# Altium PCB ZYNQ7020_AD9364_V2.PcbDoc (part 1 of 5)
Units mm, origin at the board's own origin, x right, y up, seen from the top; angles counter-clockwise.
Board outline 88.95 x 91.52 mm, 4 copper layers (Top Layer, Layer 1, Layer 2, Bottom Layer), stack 0.603 mm thick; 285 components, 278 nets, 1497 pads, 1247 vias.
Unrouted connection lines stored in the file: 367.
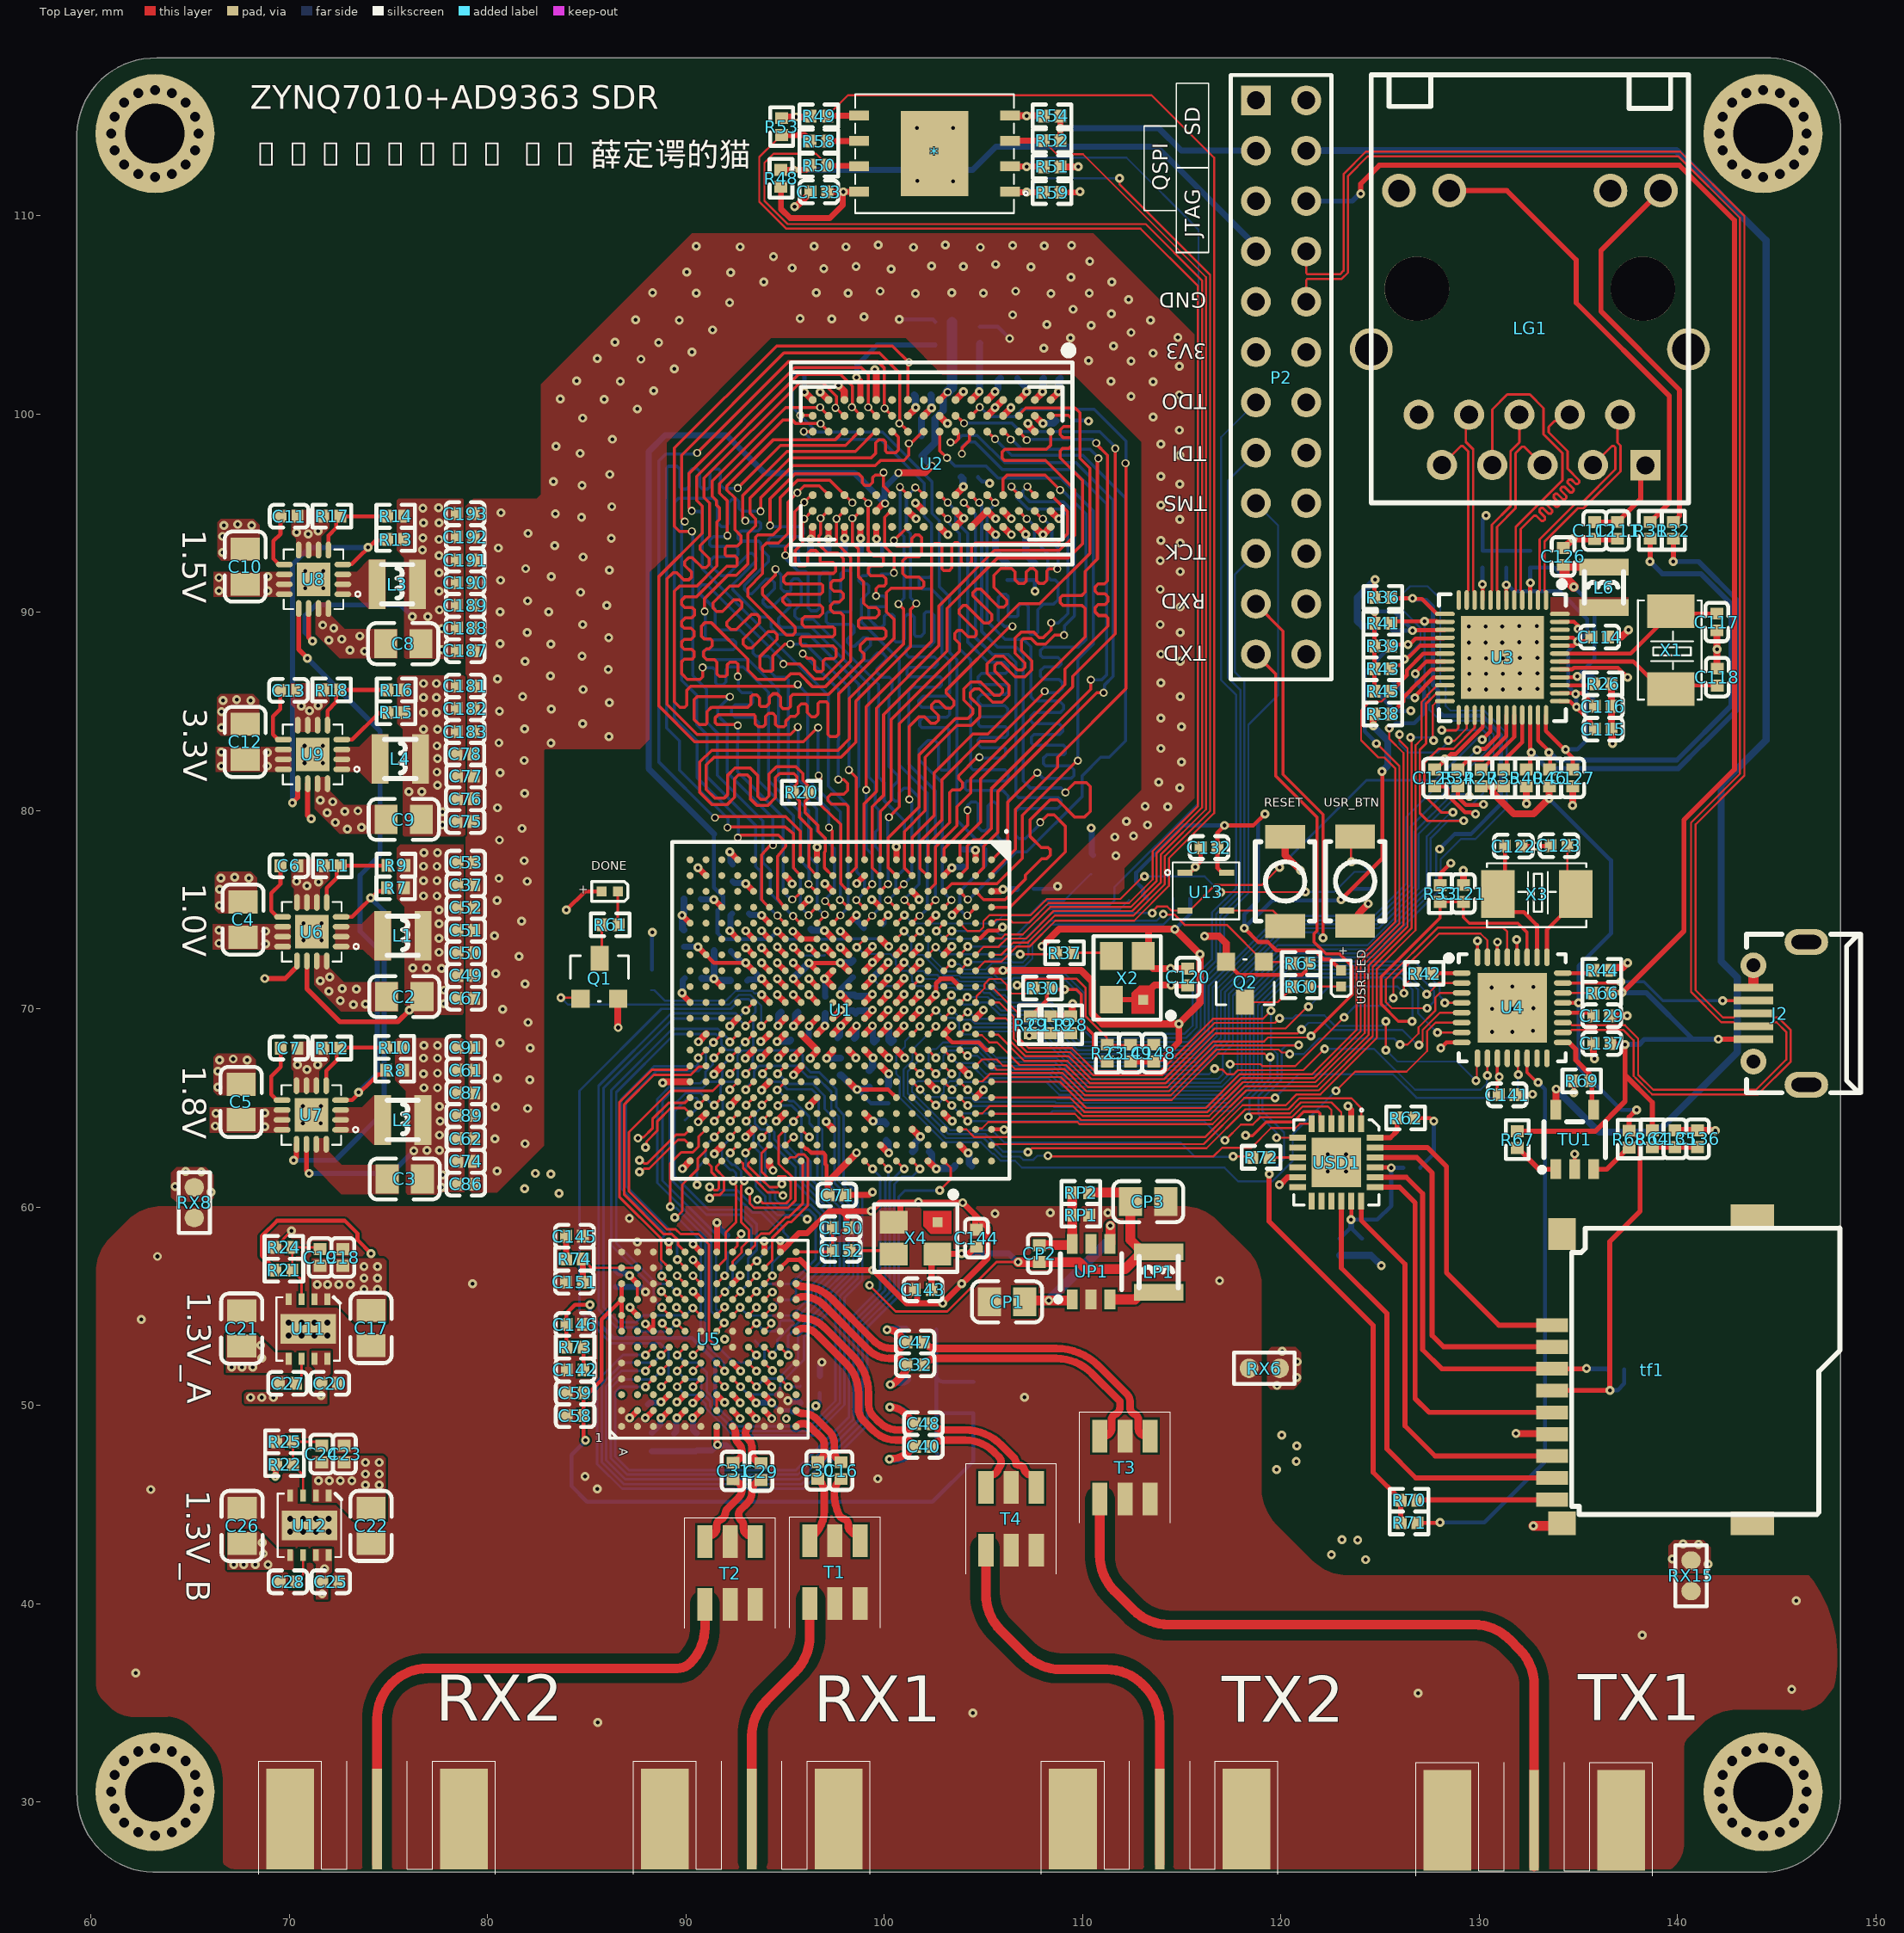
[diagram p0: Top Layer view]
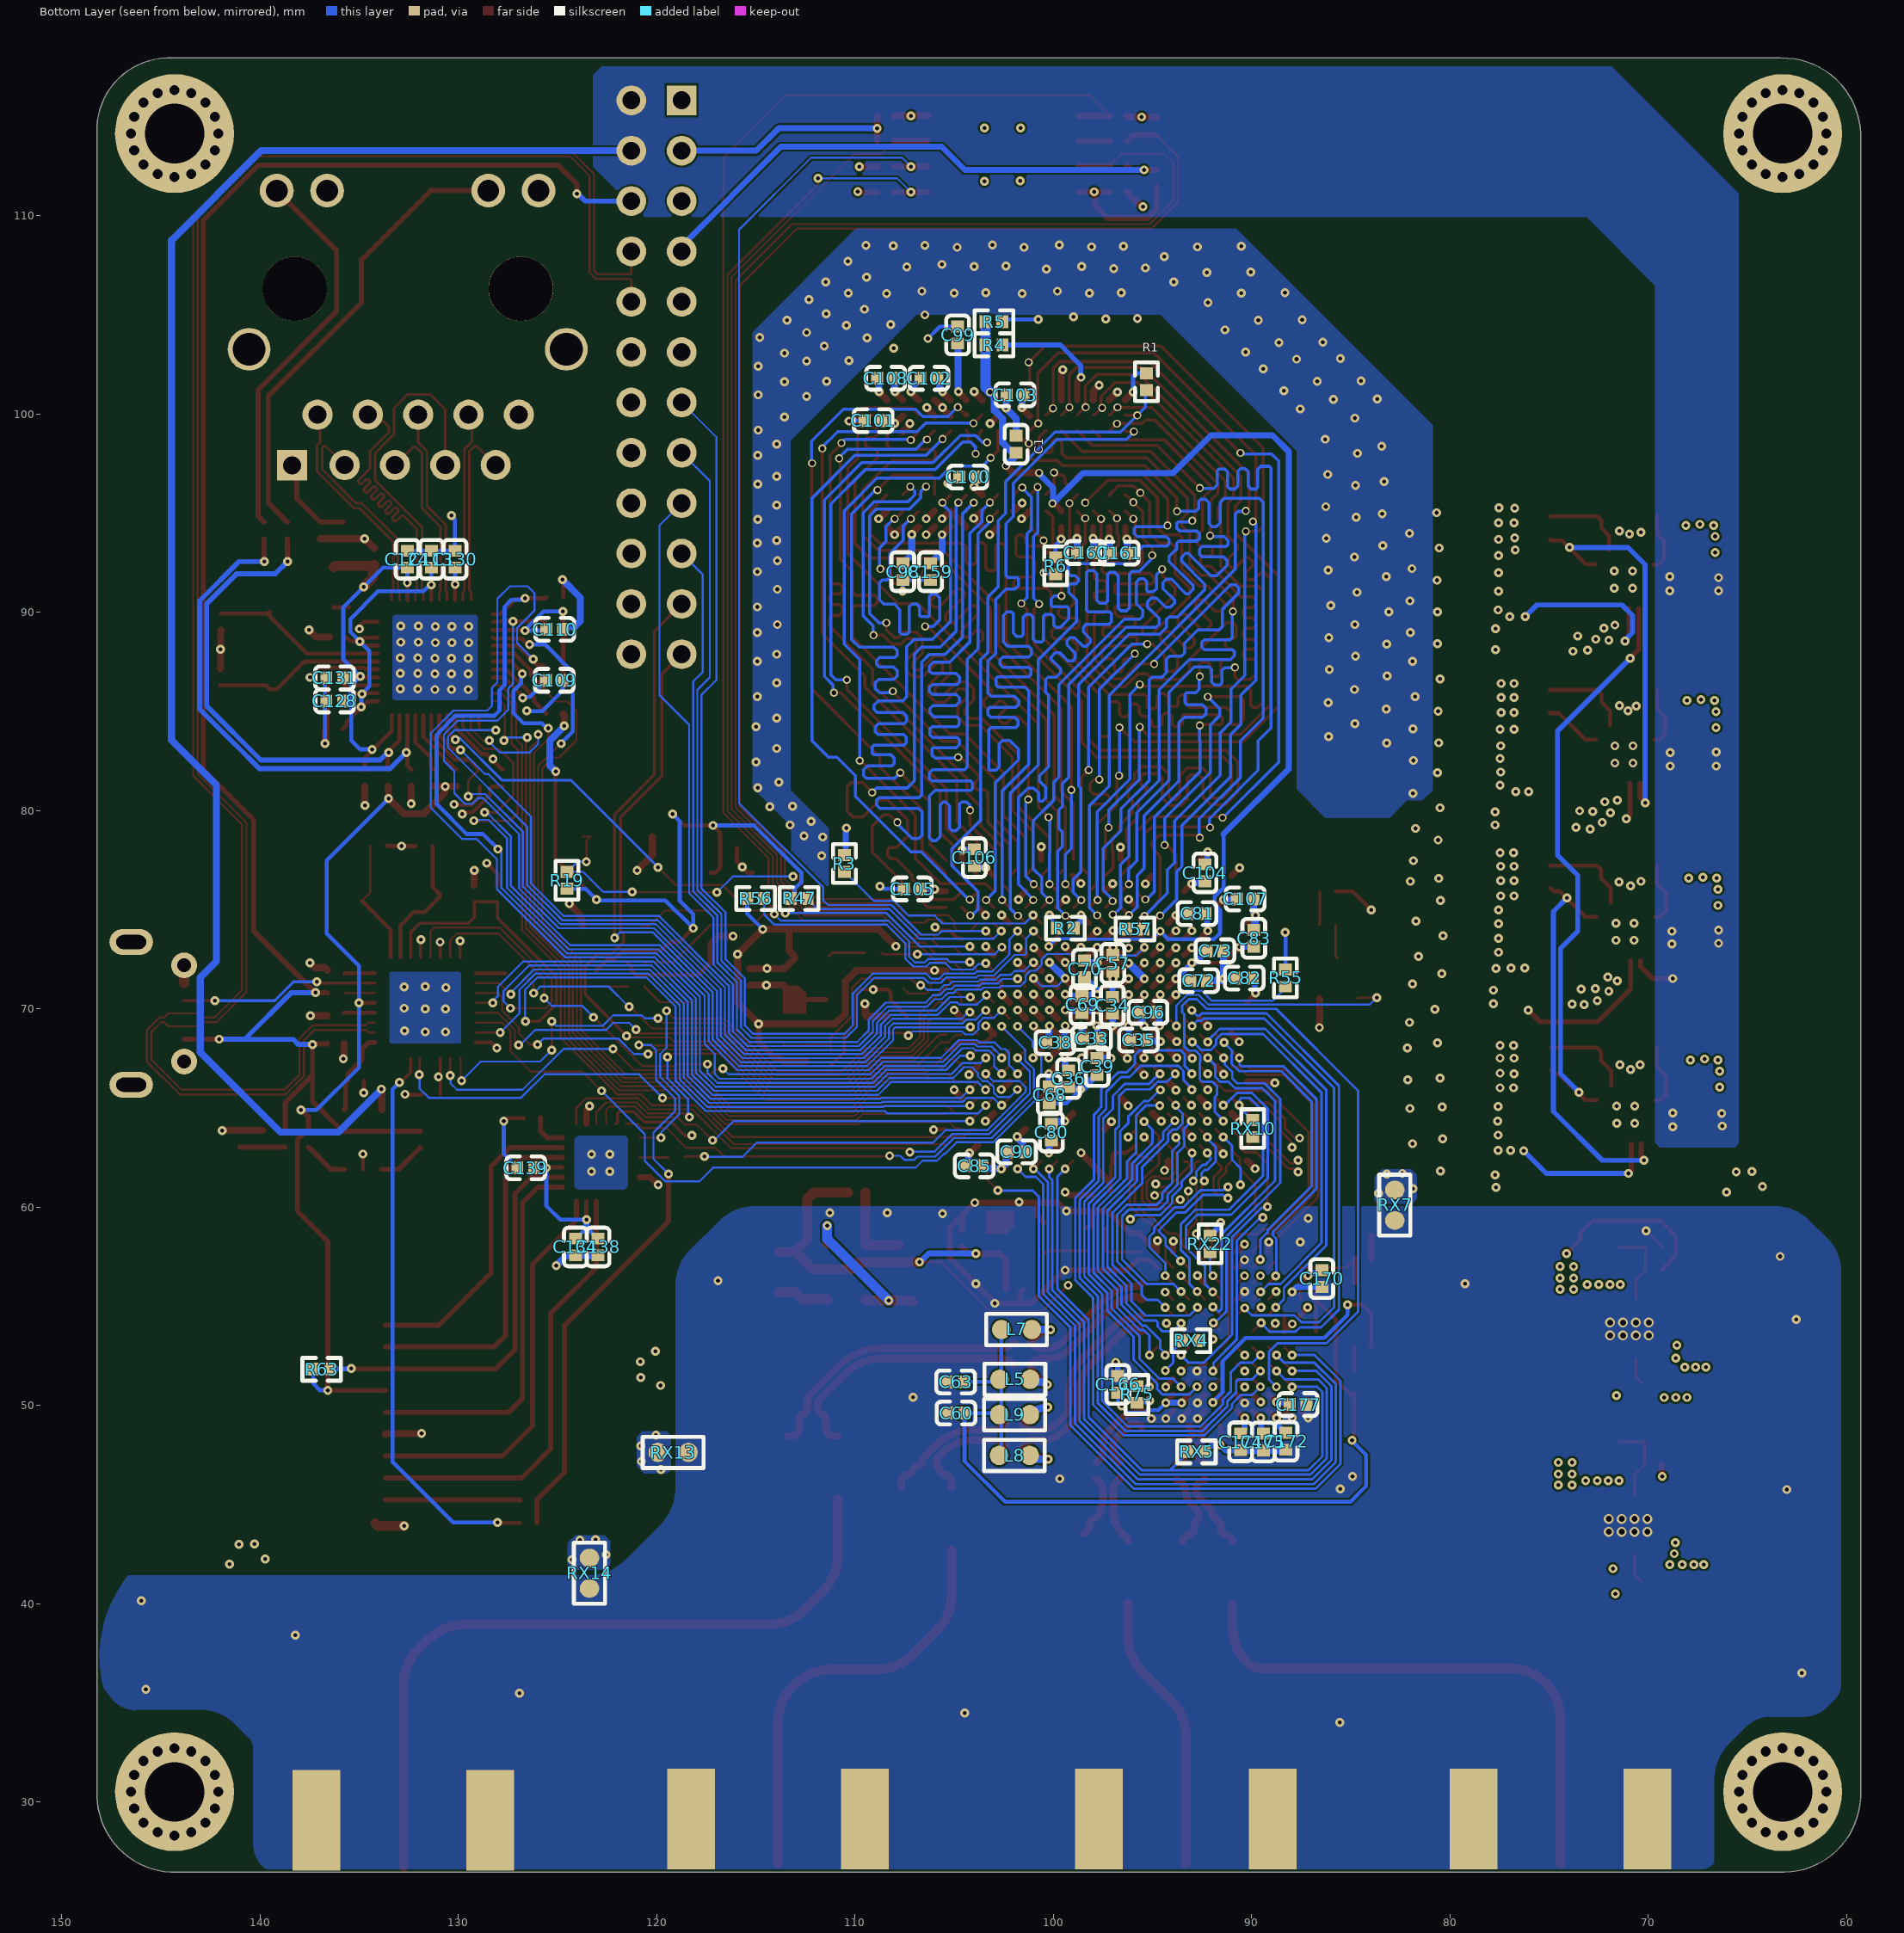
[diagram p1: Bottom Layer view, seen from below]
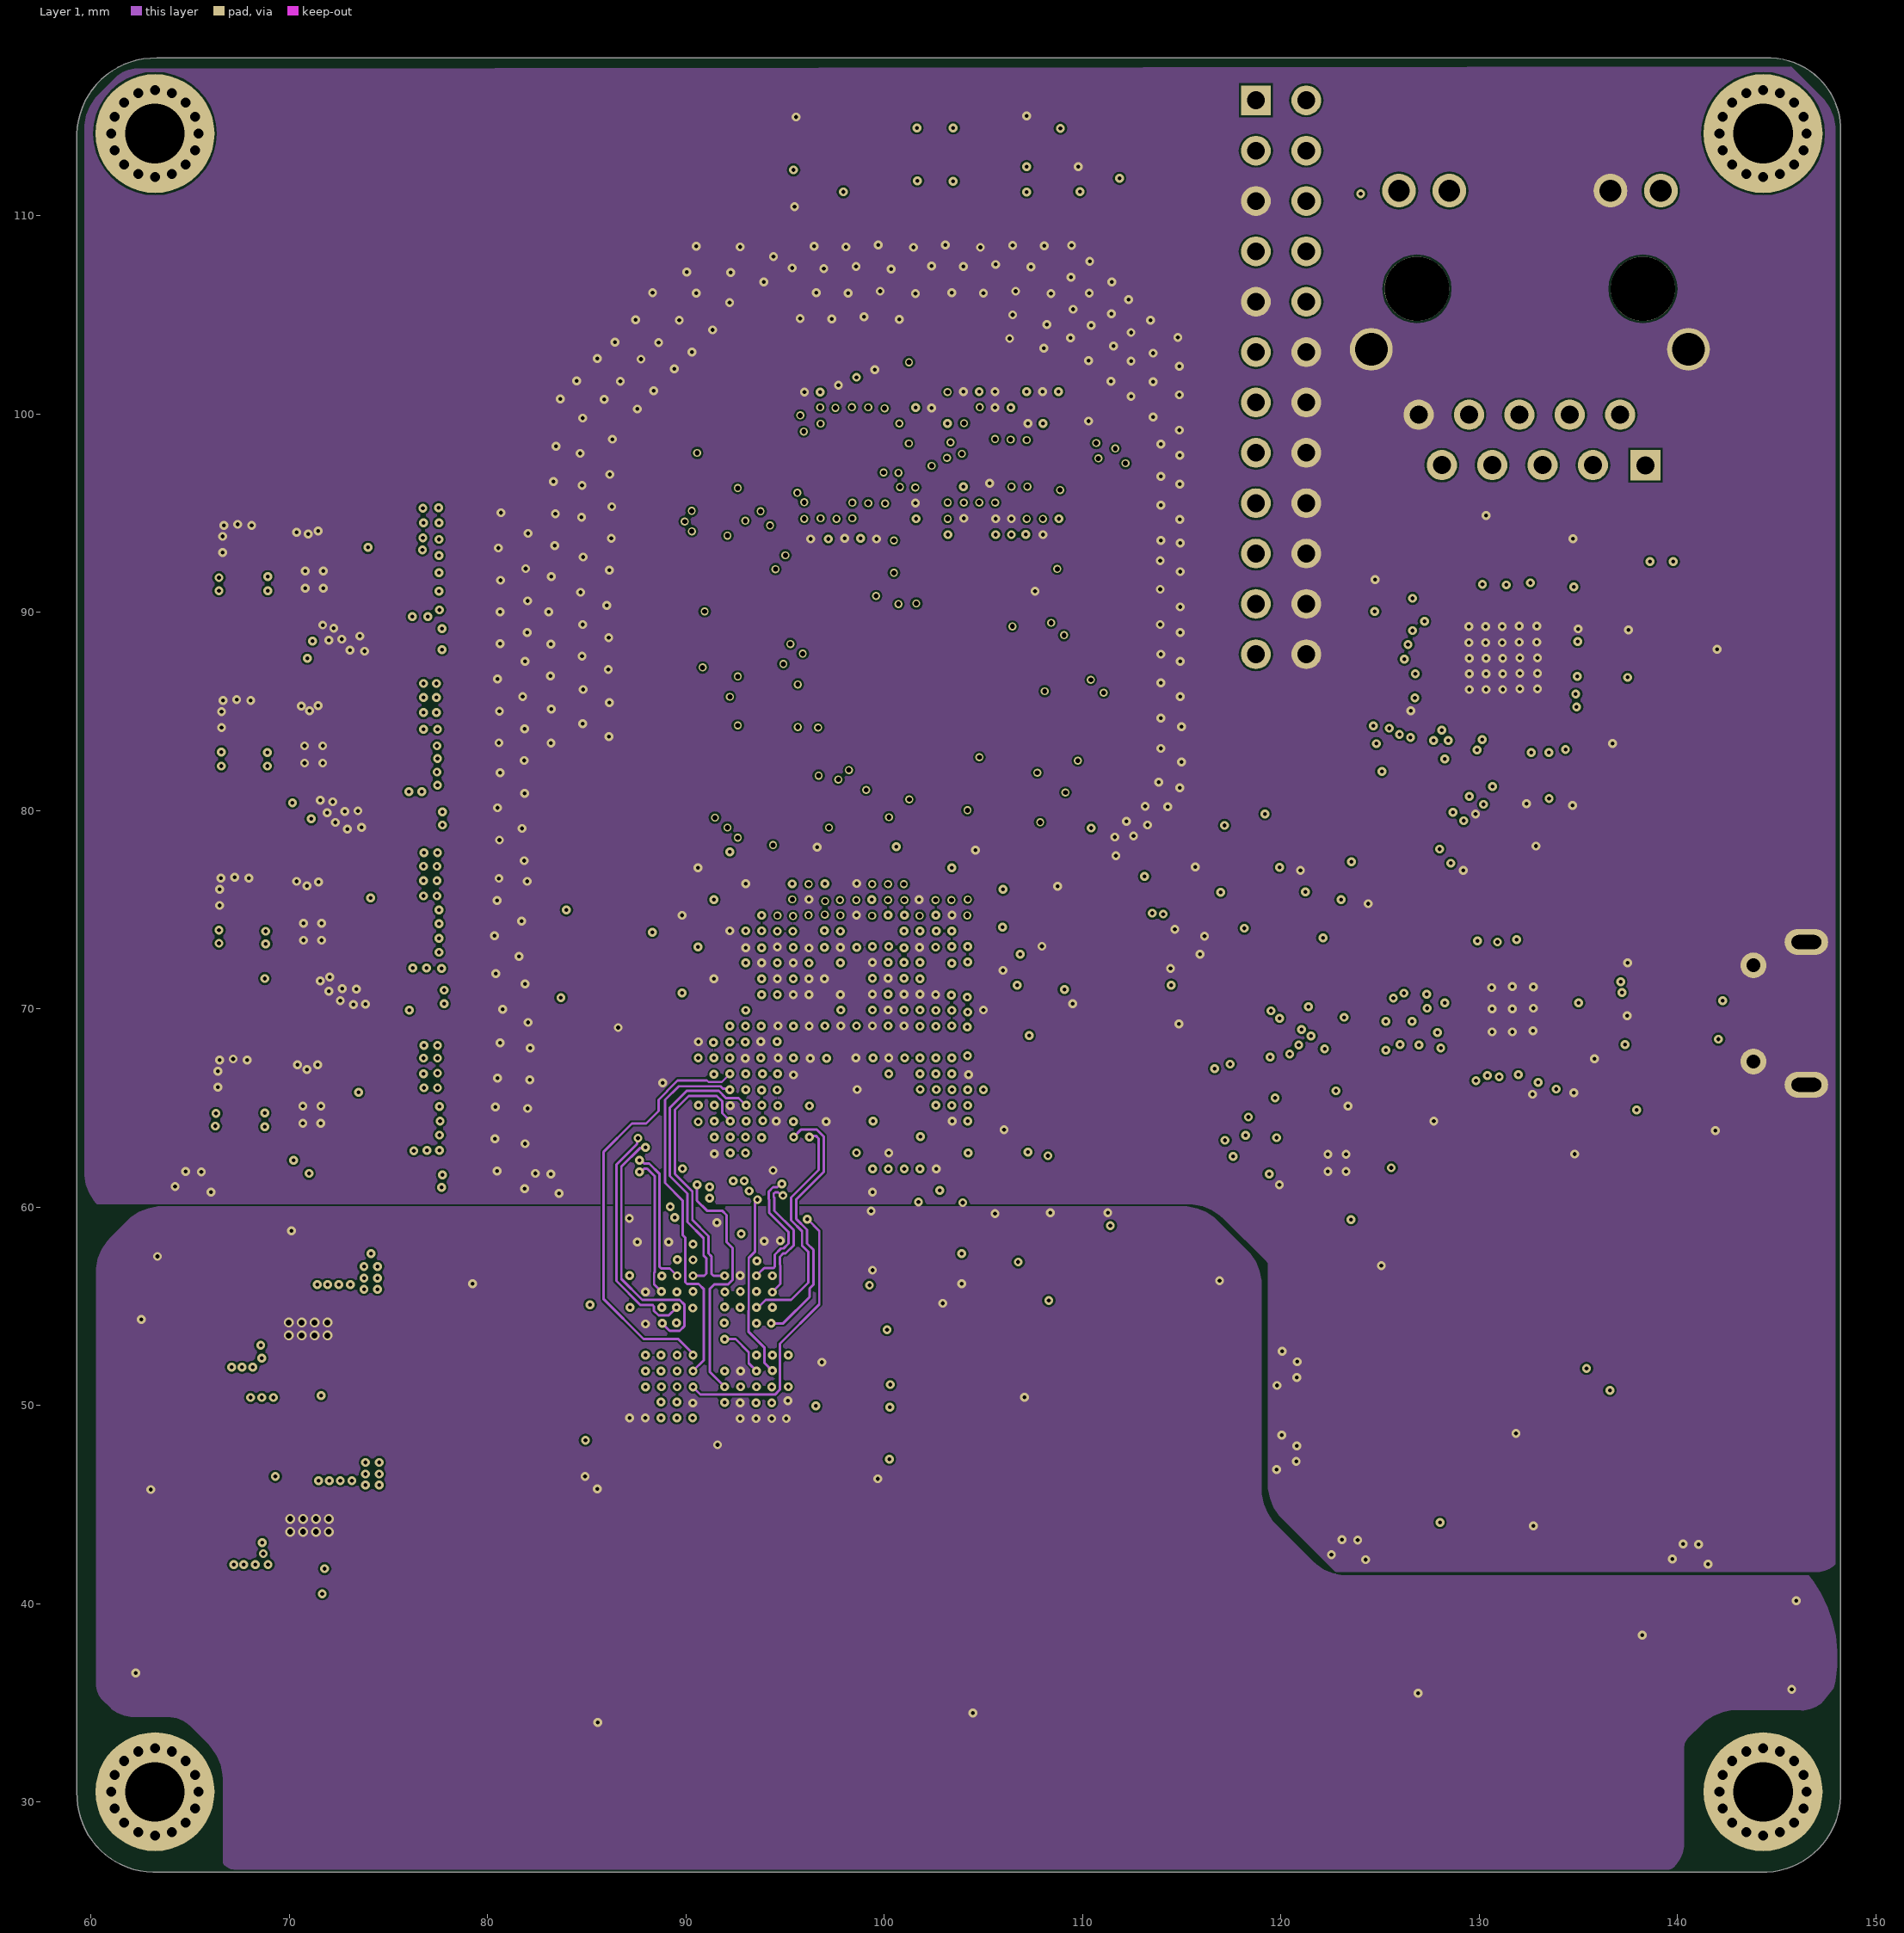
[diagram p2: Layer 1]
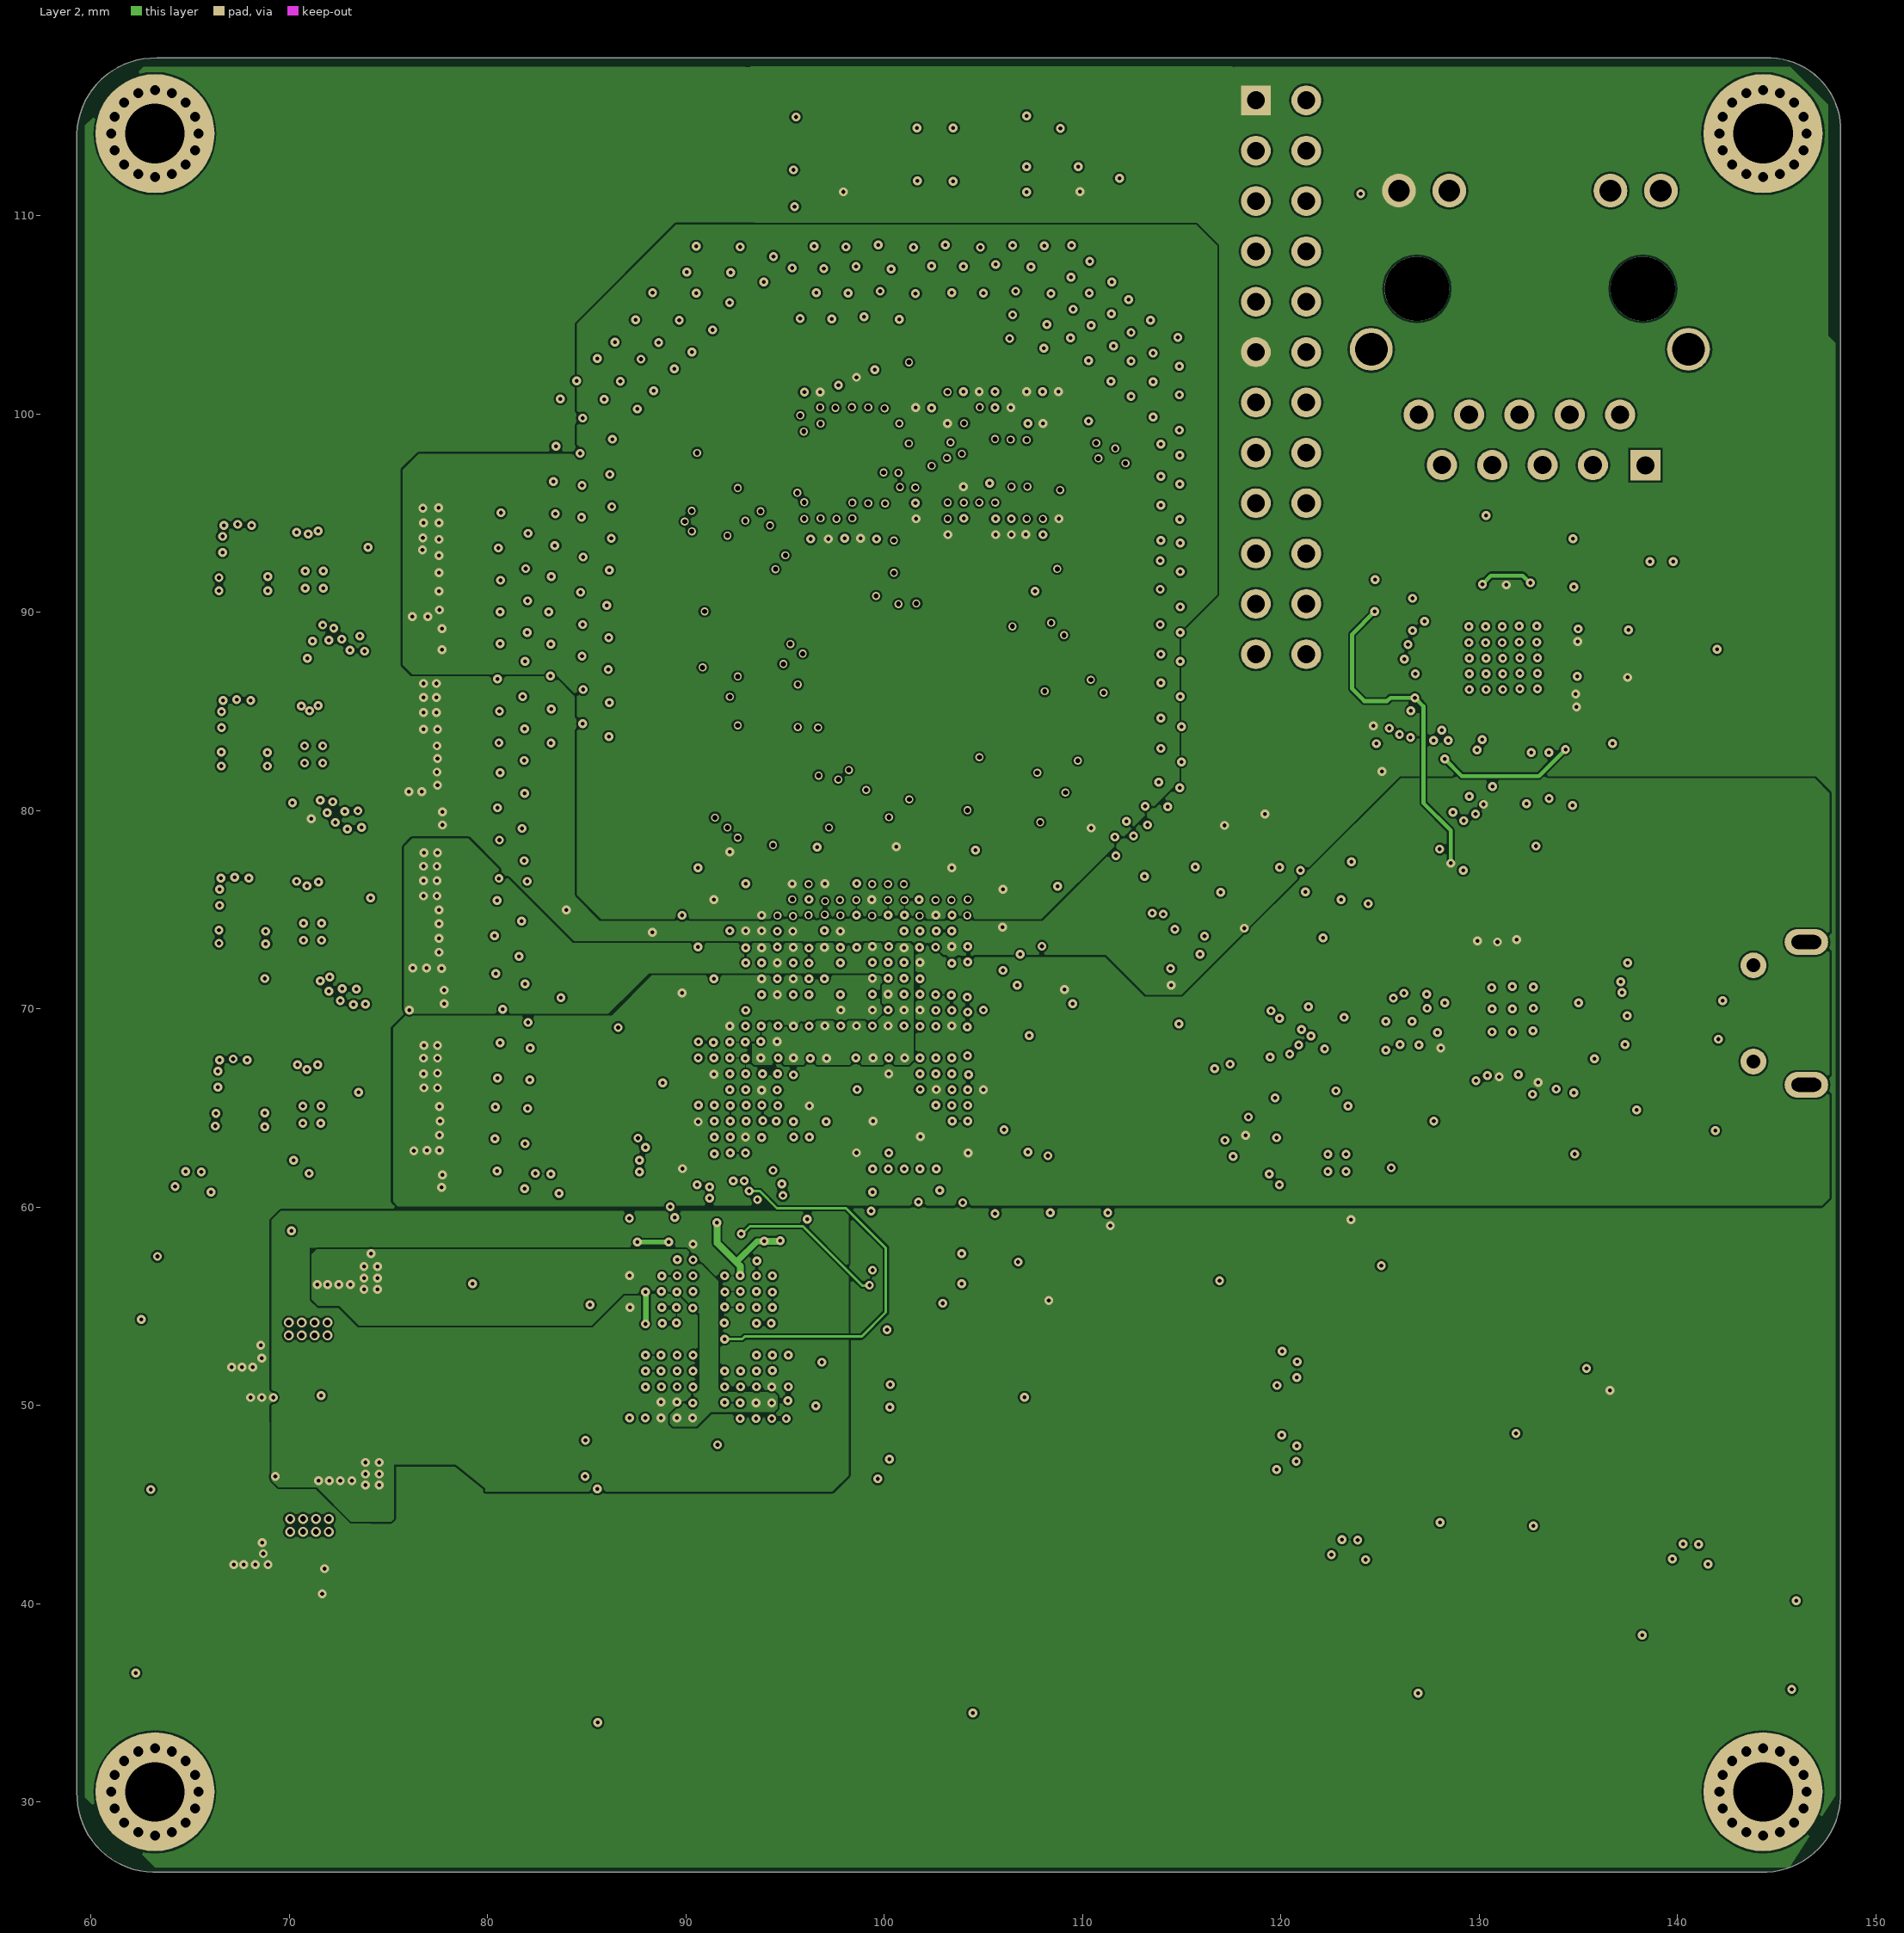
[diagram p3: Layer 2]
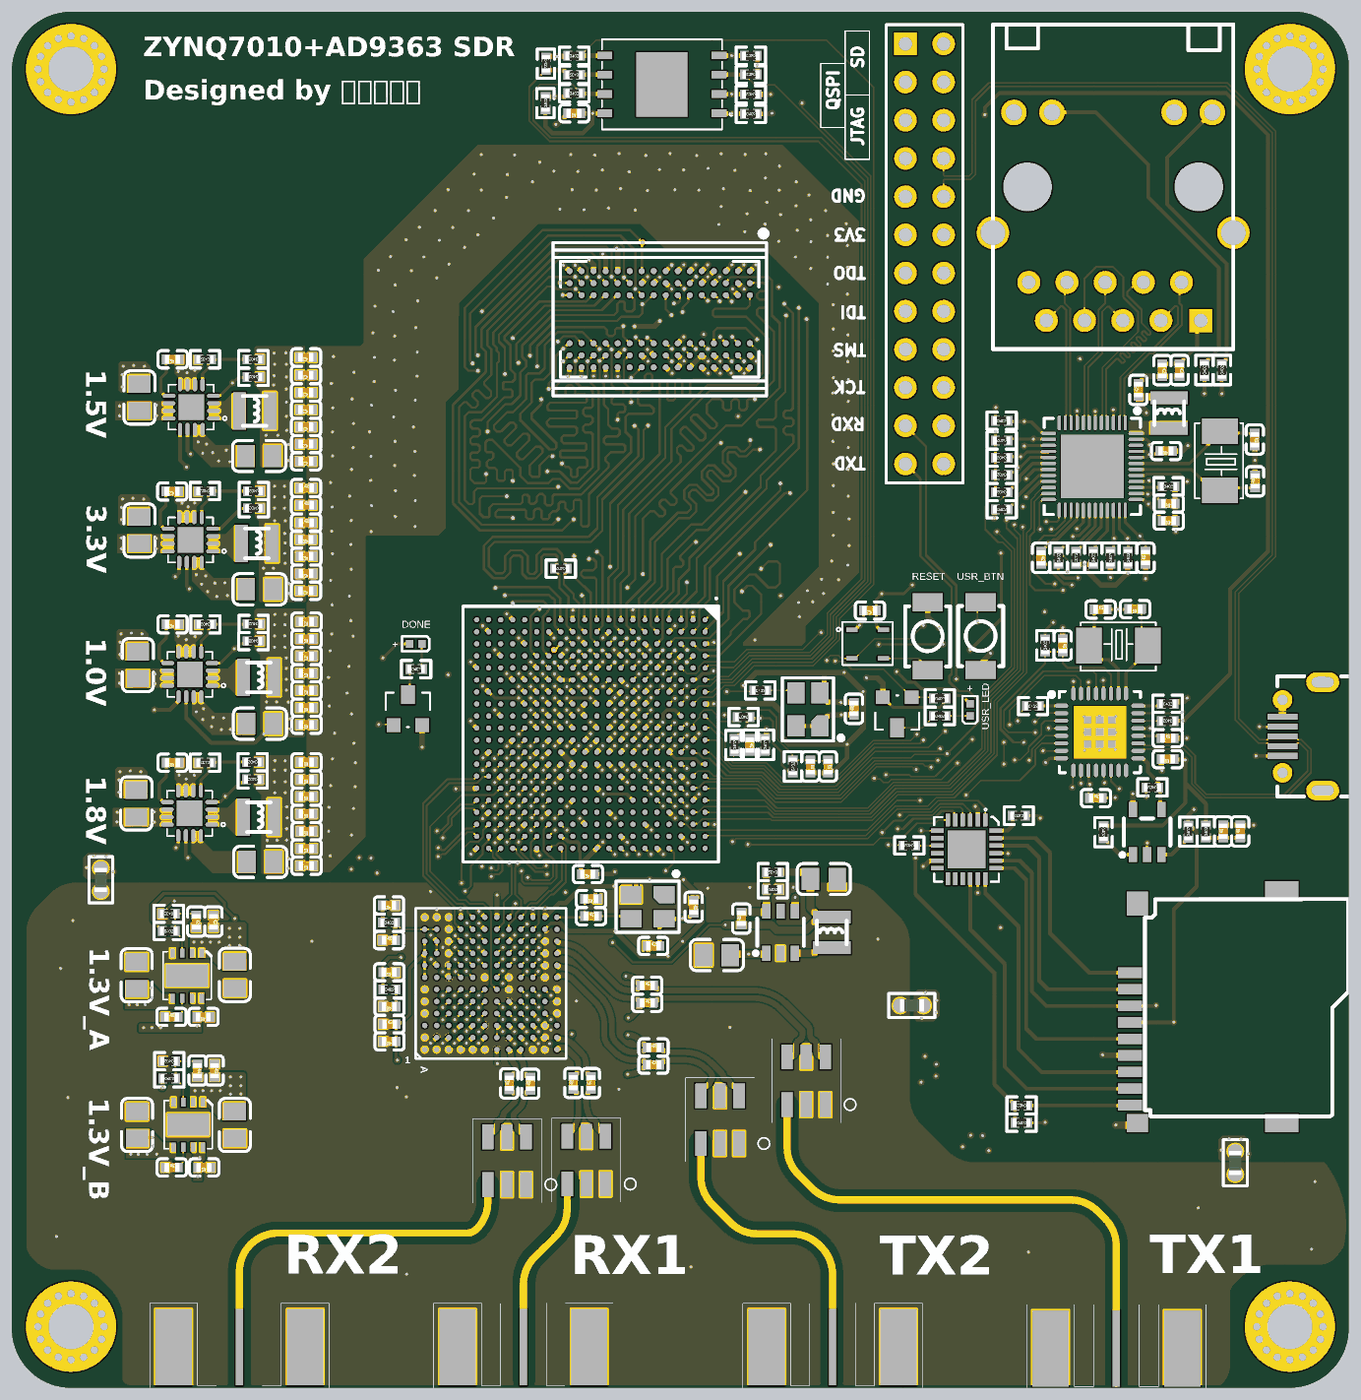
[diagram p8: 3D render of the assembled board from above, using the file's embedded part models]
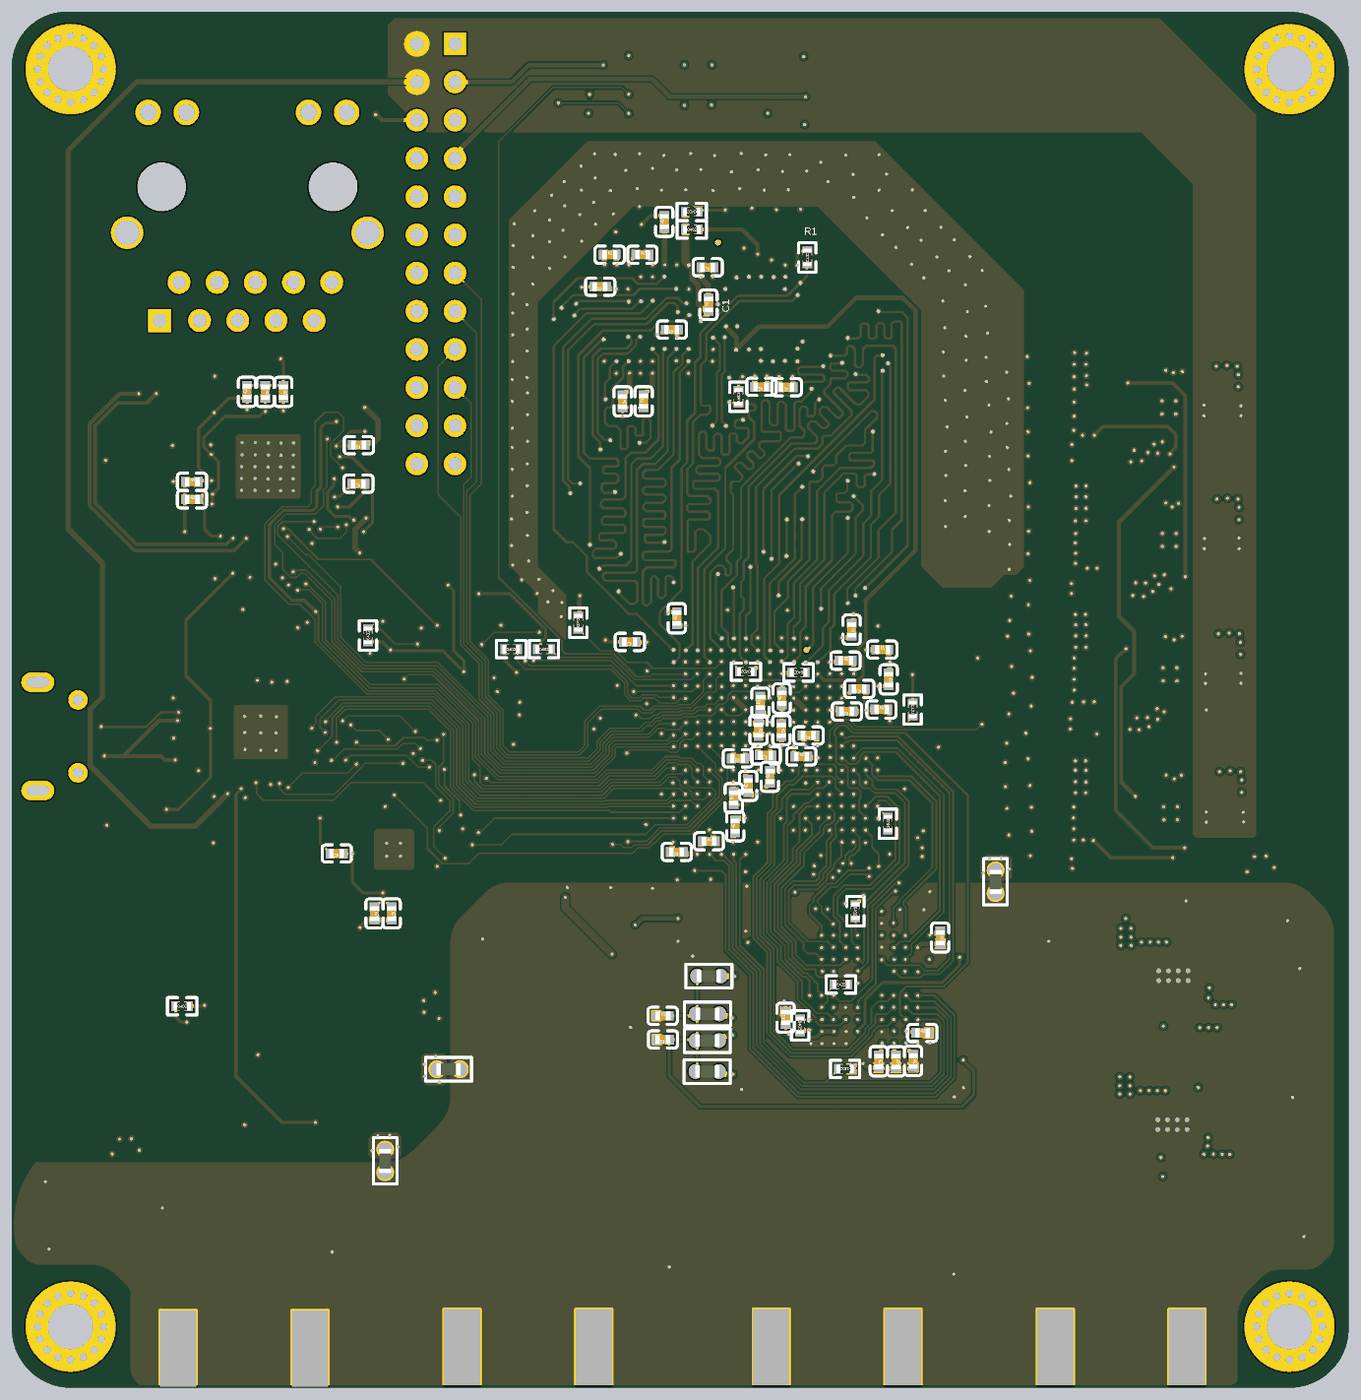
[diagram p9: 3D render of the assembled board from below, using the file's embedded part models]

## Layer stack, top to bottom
Top Solder: solder mask 0.0102, Solder Resist, Dk 3.5
Top Layer: signal copper 0.0356
Dielectric 2: prepreg 0.0711, PP-006, Dk 4.1
Layer 1: signal copper 0.035
Dielectric 1: dielectric 0.32, FR-4, Dk 4.8
Layer 2: signal copper 0.035
Dielectric 3: prepreg 0.0711, PP-006, Dk 4.1
Bottom Layer: signal copper 0.0356
Bottom Solder: solder mask 0.0102, Solder Resist, Dk 3.5

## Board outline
59.284,30.48 ccw(c63.221,30.378) 63.119,26.441 144.196,26.441 ccw(c144.297,30.378) 148.234,30.277 148.234,114.504 ccw(c144.603,114.326) 144.424,117.958 63.322,117.958 ccw(c63.221,114.021) 59.284,114.122

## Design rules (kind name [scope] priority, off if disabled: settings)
Clearance [All] p1 off: gap=0.102 ignorepadtopadclearanceinfootprint=FALSE
Clearance Clearance_1 [All] p2: gap=0.102 ignorepadtopadclearanceinfootprint=FALSE
ComponentClearance [All] p1: gap=0 collisioncheckmode=3 verticalgap=0 showdistances=FALSE
DiffPairsRouting [All] p1: maxlimit=2.54 minlimit=0.076 mostfreqgap=0.127 toplayer_minwidth=0.076 toplayer_maxwidth=2.54 toplayer_prefwidth=0.127 midlayer1_minwidth=0.076 midlayer1_maxwidth=2.54 midlayer1_prefwidth=0.127 midlayer2_minwidth=0.076 midlayer2_maxwidth=2.54 midlayer2_prefwidth=0.127 bottomlayer_minwidth=0.076 bottomlayer_maxwidth=2.54 bottomlayer_prefwidth=0.127 maxuncoupledlength=12.7
FabricationTestpoint [All] p1 off: side=3 testpointundercomponent=TRUE minsize=1.016 maxsize=2.54 preferedsize=1.524 minholesize=0 maxholesize=1.016 preferedholesize=0.813 testpointgrid=0.025 allowsidetop=TRUE allowsidebottom=TRUE usegrid=TRUE gridtolerance=0
HoleToHoleClearance [All] p1: gap=0.1 allowstackedmicrovias=TRUE
MinimumSolderMaskSliver [All] p1: minsoldermaskwidth=0.1
PlaneConnect [All] p1: planeconnectstyle=Direct reliefexpansion=0.508 reliefentries=4 reliefconductorwidth=0.254 reliefairgap=0.254
PolygonConnect [All] p1: connectstyle=Direct reliefconductorwidth=0.762 reliefentries=4 polygonreliefangle="45 Angle" airgapwidth=0.254
RoutingLayers [All] p1: top layer_v5=TRUE mid layer 1_v5=FALSE mid layer 2_v5=FALSE bottom layer_v5=TRUE
RoutingVias [All] p1: holewidth=0.711 width=1.27 viastyle="Through Hole" minholewidth=0.025 minwidth=0.051 maxholewidth=12.7 maxwidth=12.7
SilkToSilkClearance [All] p1 off: silktosilkclearance=0.254
SilkToSolderMaskClearance [IsPad] p1 off: minsilkscreentomaskgap=0.254 clearancetoexposedcopper=TRUE
SolderMaskExpansion [All] p1: expansion=0.102 istentingtop=FALSE
Width [All] p1: maxlimit=2.54 minlimit=0.025 preferedwidth=0.102
21 further rules are at their usual default settings.

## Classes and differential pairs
net class DQ815: DDR3_DM1 DDR3_DQ8 DDR3_DQ9 DDR3_DQ10 DDR3_DQ11 DDR3_DQ12 DDR3_DQ13 DDR3_DQ14 DDR3_DQ15 DDR3_DQS1_N DDR3_DQS1_P
net class DQ07: DDR3_DM0 DDR3_DQ0 DDR3_DQ1 DDR3_DQ2 DDR3_DQ3 DDR3_DQ4 DDR3_DQ5 DDR3_DQ6 DDR3_DQ7 DDR3_DQS0_N DDR3_DQS0_P
net class ADDRES: DDR3_A0 DDR3_A1 DDR3_A2 DDR3_A3 DDR3_A4 DDR3_A5 DDR3_A6 DDR3_A7 DDR3_A8 DDR3_A9 DDR3_A10 DDR3_A11 DDR3_A12 DDR3_A13 DDR3_A14 DDR3_BA0 DDR3_BA1 DDR3_BA2 DDR3_CAS DDR3_CK_N DDR3_CK_P DDR3_CKE DDR3_CS DDR3_ODT DDR3_RAS DDR3_WE
component class "08 BALUN": C16 C29 C30 C31 C32 C40 C47 C48 C58 C59 C60 C63 L5 L7 L8 L9 RX1 RX2 T1 T2 T3 T4 TX1 TX2 U5
component class "07 AD9363": C142 C143 C144 C145 C146 C150 C151 C152 C166 C170 C172 C174 C175 C177 CP1 CP2 CP3 LP1 R73 R74 R75 RP1 RP2 RX4 RX5 RX6 RX7 RX8 RX10 RX13 RX14 RX15 RX22 UP1 X4
component class "06 ZYNQ_POWER": C33 C34 C35 C36 C37 C38 C39 C49 C50 C51 C52 C53 C57 C61 C62 C67 C68 C69 C70 C71 C72 C73 C74 C75 C76 C77 C78 C80 C81 C82 C83 C85 C86 C87 C89 C90 C91 C96 C98 C99 C100 C101 C102 C103 C104 C105 C106 C107 C108 C148 C149 C181 C182 C183 R23
component class "05 POWER-SUPPLY": C2 C3 C4 C5 C6 C7 C8 C9 C10 C11 C12 C13 C17 C18 C19 C20 C21 C22 C23 C24 C25 C26 C27 C28 L1 L2 L3 L4 R7 R8 R9 R10 R11 R12 R13 R14 R15 R16 R17 R18 R21 R22 R24 R25 U6 U7 U8 U9 U11 U12
component class "04 ZYNQ_BANK0": * C133 C134 C135 C136 C137 C138 C139 C141 DONE J2 P2 Q1 Q2 R47 R48 R49 R50 R51 R52 R53 R54 R55 R56 R57 R58 R59 R60 R61 R62 R63 R64 R65 R66 R67 R68 R69 R70 R71 R72 tf1 TU1 USD1 USR_LED
component class "03 ZYNQ_PL-BANK34-35": U1
component class "02 ZYNQ_PS-BANK500-501": C109 C110 C111 C112 C113 C114 C115 C116 C117 C118 C119 C120 C121 C122 C123 C124 C125 C126 C127 C128 C129 C130 C131 C132 L6 LG1 R19 R26 R27 R28 R29 R30 R31 R32 R33 R34 R35 R36 R37 R38 R39 R40 R41 R42 R43 R44 R45 R46 RESET U3 U4 U13 USR_BTN X1 X2 X3
component class "01 ZYNQ_DDR": C1 C159 C160 C161 C187 C188 C189 C190 C191 C192 C193 R1 R2 R3 R4 R5 R6 R20 U2
differential pair TX1AN: +TX1AN_P -TX1AN_N
differential pair USB_OTG: +USB_OTG_P -USB_OTG_N
differential pair TX_FRAME: +TX_FRAME_P -TX_FRAME_N
differential pair TX_D5: +TX_D5_P -TX_D5_N
differential pair TX_D4: +TX_D4_P -TX_D4_N
differential pair TX_D3: +TX_D3_P -TX_D3_N
differential pair TX_D2: +TX_D2_P -TX_D2_N
differential pair TX_D1: +TX_D1_P -TX_D1_N
differential pair TX_D0: +TX_D0_P -TX_D0_N
differential pair TX1B: +TX1B_P -TX1B_N
differential pair TX1BN: +TX1BN_P -TX1BN_N
differential pair TX1A: +TX1A_P -TX1A_N
differential pair RX_FRAME: +RX_FRAME_P -RX_FRAME_N
differential pair RX_D5: +RX_D5_P -RX_D5_N
differential pair RX_D4: +RX_D4_P -RX_D4_N
differential pair RX_D3: +RX_D3_P -RX_D3_N
differential pair RX_D2: +RX_D2_P -RX_D2_N
differential pair RX_D1: +RX_D1_P -RX_D1_N
differential pair RX_D0: +RX_D0_P -RX_D0_N
differential pair RX1B: +RX1B_P -RX1B_N
differential pair RX1BN: +RX1BN_P -RX1BN_N
differential pair RX1A: +RX1A_P -RX1A_N
differential pair RX1AN: +RX1AN_P -RX1AN_N
differential pair PHY_MDI3: +PHY_MDI3_P -PHY_MDI3_N
differential pair PHY_MDI2: +PHY_MDI2_P -PHY_MDI2_N
differential pair PHY_MDI1: +PHY_MDI1_P -PHY_MDI1_N
differential pair PHY_MDI0: +PHY_MDI0_P -PHY_MDI0_N
differential pair FB_CLK: +FB_CLK_P -FB_CLK_N
differential pair DDR3_DQS1: +DDR3_DQS1_P -DDR3_DQS1_N
differential pair DDR3_DQS0: +DDR3_DQS0_P -DDR3_DQS0_N
differential pair DDR3_CK: +DDR3_CK_P -DDR3_CK_N
differential pair DATA_CLK: +DATA_CLK_P -DATA_CLK_N

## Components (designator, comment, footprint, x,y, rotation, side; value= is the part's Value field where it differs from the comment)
* "W25Q128" W25Q256 102.54,113.132 r90 top
C1 "104" LC-0402_C 101.879,98.476 r90 bottom
C2 "10μF" LC-0805_C 75.794,70.612 r0 top
C3 "10μF" LC-0805_C 75.819,61.417 r0 top
C4 "10μF" LC-0805_C 67.666,74.498 r270 top
C5 "10μF" LC-0805_C 67.564,65.303 r270 top
C6 "0.1μF" LC-0402_C 69.977,77.216 r180 top
C7 "0.1μF" LC-0402_C 69.984,68.021 r180 top
C8 "10μF" LC-0805_C 75.743,88.417 r0 top
C9 "10μF" LC-0805_C 75.768,79.553 r0 top
C10 "10μF" LC-0805_C 67.767,92.305 r270 top
C11 "0.1μF" LC-0402_C 69.984,94.844 r180 top
C12 "10μF" LC-0805_C 67.767,83.464 r270 top
C13 "0.1μF" LC-0402_C 69.958,86.055 r180 top
C16 "18p" LC-0402_C 97.815,46.704 r90 top
C17 "2.2μF" LC-0805_C 74.117,53.899 r90 top
C18 "0.1μF" LC-0402_C 72.695,57.455 r270 top
C19 "3.3nF" LC-0402_C 71.552,57.455 r270 top
C20 "2.2μF" LC-0402_C 72.034,51.105 r180 top
C21 "0.1μF" LC-0805_C 67.589,53.873 r270 top
C22 "2.2μF" LC-0805_C 74.117,43.918 r90 top
C23 "0.1μF" LC-0402_C 72.771,47.542 r270 top
C24 "3.3nF" LC-0402_C 71.628,47.542 r270 top
C25 "2.2μF" LC-0402_C 72.085,41.097 r180 top
C26 "0.1μF" LC-0805_C 67.615,43.917 r270 top
C27 "0.1μF" LC-0402_C 69.901,51.105 r0 top
C28 "0.1μF" LC-0402_C 69.926,41.097 r0 top
C29 "18p" LC-0402_C 93.777,46.66 r90 top
C30 "18p" LC-0402_C 96.647,46.717 r90 top
C31 "18p" LC-0402_C 92.38,46.685 r90 top
C32 "18p" LC-0402_C 101.556,52.045 r0 top
C33 "10μF" LC-0402_C 98.069,68.504 r0 bottom
C34 "10μF" LC-0402_C 97.028,70.18 r270 bottom
C35 "10μF" LC-0402_C 95.707,68.428 r180 bottom
C36 "10μF" LC-0402_C 99.238,66.472 r90 bottom
C37 "10μF" LC-0402_C 78.892,76.251 r180 top
C38 "10μF" LC-0402_C 99.924,68.301 r0 bottom
C39 "10μF" LC-0402_C 97.79,67.081 r90 bottom
C40 "18p" LC-0402_C 101.974,47.93 r0 top
C47 "18p" LC-0402_C 101.556,53.188 r0 top
C48 "18p" LC-0402_C 101.981,49.073 r0 top
C49 "10μF" LC-0402_C 78.892,71.679 r180 top
C50 "10μF" LC-0402_C 78.892,72.822 r180 top
C51 "10μF" LC-0402_C 78.892,73.965 r180 top
C52 "10μF" LC-0402_C 78.892,75.108 r180 top
C53 "10μF" LC-0402_C 78.892,77.394 r180 top
C57 "10μF" LC-0402_C 97.003,72.288 r90 bottom
C58 "10μ" LC-0402_C 84.411,49.479 r180 top
C59 "0.001μ" LC-0402_C 84.411,50.622 r0 top
C60 "10μ" LC-0402_C 104.909,49.606 r0 bottom
C61 "10μF" LC-0402_C 78.892,66.904 r180 top
C62 "10μF" LC-0402_C 78.899,63.449 r180 top
C63 "0.001μ" LC-0402_C 104.927,51.181 r180 bottom
C67 "10μF" LC-0402_C 78.892,70.536 r180 top
C68 "10μF" LC-0402_C 100.203,65.659 r90 bottom
C69 "10μF" LC-0402_C 98.552,70.206 r270 bottom
C70 "10μF" LC-0402_C 98.425,72.009 r90 bottom
C71 "10μF" LC-0402_C 97.612,60.604 r180 top
C72 "10μF" LC-0402_C 92.666,71.425 r0 bottom
C73 "10μF" LC-0402_C 91.846,72.923 r0 bottom
C74 "10μF" LC-0402_C 78.892,62.306 r180 top
C75 "10μF" LC-0402_C 78.86,79.451 r180 top
C76 "10μF" LC-0402_C 78.874,80.594 r180 top
C77 "10μF" LC-0402_C 78.881,81.737 r180 top
C78 "10μF" LC-0402_C 78.855,82.855 r180 top
C80 "10μF" LC-0402_C 100.101,63.779 r90 bottom
C81 "10μF" LC-0402_C 92.761,74.803 r180 bottom
C82 "10μF" LC-0402_C 90.373,71.552 r180 bottom
C83 "10μF" LC-0402_C 89.891,73.558 r270 bottom
C85 "10μF" LC-0402_C 103.988,62.078 r0 bottom
C86 "10μF" LC-0402_C 78.892,61.163 r180 top
C87 "10μF" LC-0402_C 78.892,65.761 r180 top
C89 "10μF" LC-0402_C 78.892,64.618 r180 top
C90 "10μF" LC-0402_C 101.854,62.789 r180 bottom
C91 "10μF" LC-0402_C 78.892,68.047 r180 top
C96 "10μF" LC-0402_C 95.225,69.825 r0 bottom
C98 "10μF" LC-0402_C 107.594,92.05 r270 bottom
C99 "10μF" LC-0402_C 104.826,103.988 r90 bottom
C100 "10μF" LC-0402_C 104.311,96.825 r0 bottom
C101 "10μF" LC-0402_C 109.086,99.67 r0 bottom
C102 "10μF" LC-0402_C 106.28,101.803 r180 bottom
C103 "10μF" LC-0402_C 101.93,100.965 r0 bottom
C104 "10μF" LC-0402_C 92.354,76.86 r270 bottom
C105 "10μF" LC-0402_C 107.112,76.048 r0 bottom
C106 "10μF" LC-0402_C 103.988,77.622 r90 bottom
C107 "10μF" LC-0402_C 90.322,75.54 r180 bottom
C108 "10μF" LC-0402_C 108.458,101.803 r180 bottom
C109 "1μ" LC-0402_C 125.172,86.571 r0 bottom
C110 "1μ" LC-0402_C 125.147,89.136 r0 bottom
C111 "1μ" LC-0402_C 136.982,94.132 r270 top
C112 "0.1μ" LC-0402_C 135.839,94.126 r270 top
C113 "1μ" LC-0402_C 131.369,92.678 r270 bottom
C114 "1μ" LC-0402_C 136.086,88.748 r180 top
C115 "1μ" LC-0402_C 136.265,84.107 r180 top
C116 "1μ" LC-0402_C 136.265,85.25 r180 top
C117 "18p" LC-0402_C 141.987,89.51 r270 top
C118 "18p" LC-0402_C 142.012,86.73 r90 top
C119 "0.01μ" LC-0402_C 108.389,69.2 r270 top
C120 "0.1μ" LC-0402_C 115.316,71.603 r90 top
C121 "10μ" LC-0402_C 129.21,75.819 r270 top
C122 "18p" LC-0402_C 131.731,78.207 r0 top
C123 "18p" LC-0402_C 134.029,78.232 r180 top
C124 "1μ" LC-0402_C 132.588,92.678 r90 bottom
C125 "1μ" LC-0402_C 127.763,81.643 r270 top
C126 "1μ" LC-0402_C 134.239,92.812 r90 top
C127 "1μ" LC-0402_C 134.722,81.643 r90 top
C128 "1μ" LC-0402_C 136.246,85.529 r180 bottom
C129 "4.7μ" LC-0402_C 136.188,69.647 r0 top
C130 "1μ" LC-0402_C 130.175,92.678 r270 bottom
C131 "1μ" LC-0402_C 136.246,86.698 r180 bottom
C132 "0.1μ" LC-0402_C 116.383,78.13 r180 top
C133 "0.1μ" LC-0402_C 96.705,111.201 r180 top
C134 "0.1μ" LC-0402_C 124.104,57.988 r270 bottom
C135 "4.7μ" LC-0402_C 139.878,63.442 r90 top
C136 "4.7μ" LC-0402_C 141.021,63.442 r90 top
C137 "4.7μ" LC-0402_C 136.195,68.25 r180 top
C138 "0.1μ" LC-0402_C 122.961,57.988 r270 bottom
C139 "10μ" LC-0402_C 126.612,61.976 r0 bottom
C141 "0.1μ" LC-0402_C 131.42,65.659 r0 top
C142 "1μ" LC-0402_C 84.411,51.791 r180 top
C143 "0.1μ" LC-0402_C 101.962,55.829 r0 top
C144 "10μ" LC-0402_C 104.648,58.427 r270 top
C145 "1μ" LC-0402_C 84.379,58.522 r180 top
C146 "0.001μ" LC-0402_C 84.397,54.077 r180 top
C148 "10μF" LC-0402_C 113.589,67.767 r270 top
C149 "10μF" LC-0402_C 112.42,67.767 r270 top
C150 "18p" LC-0402_C 97.822,58.953 r180 top
C151 "0.001μ" LC-0402_C 84.372,56.21 r0 top
C152 "18p" LC-0402_C 97.822,57.81 r0 top
C159 "104" LC-0402_C 106.197,92.05 r90 bottom
C160 "104" LC-0402_C 98.374,93.015 r0 bottom
C161 "104" LC-0402_C 96.672,92.989 r0 bottom
C166 "1μ" LC-0402_C 96.749,51.054 r90 bottom
C170 "1μ" LC-0402_C 86.462,56.388 r270 bottom
C172 "1μ" LC-0402_C 88.265,48.184 r270 bottom
C174 "1μ" LC-0402_C 90.551,48.158 r270 bottom
C175 "0.001μ" LC-0402_C 89.408,48.152 r270 bottom
C177 "0.001μ" LC-0402_C 87.655,50.038 r180 bottom
C181 "10μF" LC-0402_C 78.86,86.284 r0 top
C182 "10μF" LC-0402_C 78.86,85.141 r0 top
C183 "10μF" LC-0402_C 78.86,83.972 r0 top
C187 "104" LC-0402_C 78.867,88.062 r180 top
C188 "104" LC-0402_C 78.867,89.205 r180 top
C189 "104" LC-0402_C 78.86,90.348 r180 top
C190 "104" LC-0402_C 78.86,91.491 r180 top
C191 "104" LC-0402_C 78.86,92.634 r180 top
C192 "104" LC-0402_C 78.86,93.802 r180 top
C193 "104" LC-0402_C 78.86,94.971 r180 top
CP1 "22uF" LC-0805_C 106.198,55.22 r0 top
CP2 "22pF" LC-0402_C 107.823,57.651 r90 top
CP3 "22uF" LC-0805_C 113.309,60.274 r180 top
DONE "LED" D0402 86.157,75.921 r0 top
J2 "microusb" "micro usb" 143.911,67.322 r90 top
L1 "2.2uH" L1008 75.717,73.685 r0 top
L2 "2.2uH" L1008 75.715,64.389 r0 top
L3 "2.2uH" L1008 75.436,91.415 r0 top
L4 "2.2uH" L1008 75.59,82.601 r0 top
L5 "330nh" LC-0603_L 101.938,51.308 r180 bottom
L6 "2.2uH" L1008 136.296,91.26 r90 top
L7 "330nh" LC-0603_L 101.854,53.823 r180 bottom
L8 "330nh" LC-0603_L 101.964,47.473 r180 bottom
L9 "330nh" LC-0603_L 101.956,49.53 r180 bottom
LG1 "HR911130C" HR911130C 132.563,104.343 r0 top
LP1 "4.7uH" L1008 113.843,56.718 r90 top
P2 "Header 12X2A" HDR2X12_CEN 118.745,115.824 r270 top
Q1 "AO3400" NMOS 85.674,72.542 r270 top
Q2 "AO3400" NMOS 118.161,70.333 r90 top
R1 "4.7K" LC-0402_R 95.301,101.625 r90 bottom
R2 "82R" LC-0402_R 99.39,74.066 r0 bottom
R3 "82R" LC-0402_R 110.541,77.324 r270 bottom
R4 "4.7K" LC-0402_R 102.99,103.48 r180 bottom
R5 "4.7K" LC-0402_R 102.997,104.648 r0 bottom
R6 "240R" LC-0402_R 99.89,92.351 r90 bottom
R7 "100K" LC-0402_R 75.362,76.098 r180 top
R8 "10K" LC-0402_R 75.311,66.904 r180 top
R9 "4.99K" LC-0402_R 75.369,77.241 r180 top
R10 "18.7K" LC-0402_R 75.311,68.047 r180 top
R11 "20K" LC-0402_R 72.161,77.216 r180 top
R12 "15K" LC-0402_R 72.136,68.021 r180 top
R13 "10K" LC-0402_R 75.362,93.675 r180 top
R14 "13K" LC-0402_R 75.362,94.844 r180 top
R15 "10K" LC-0402_R 75.38,84.938 r180 top
R16 "56.2K" LC-0402_R 75.387,86.081 r180 top
R17 "15K" LC-0402_R 72.136,94.844 r180 top
R18 "18K" LC-0402_R 72.129,86.081 r180 top
R19 "10K" LC-0402_R 124.536,76.479 r90 bottom
R20 "80.6R" LC-0402_R 95.809,80.924 r180 top
R21 "6.25K" LC-0402_R 69.723,56.82 r0 top
R22 "6.25K" LC-0402_R 69.755,47.015 r0 top
R23 "0R" LC-0402_R 111.252,67.767 r90 top
R24 "10K" LC-0402_R 69.721,57.967 r180 top
R25 "10K" LC-0402_R 69.753,48.162 r180 top
R26 "2.49K" LC-0402_R 136.246,86.393 r0 top
R27 "4.7K" LC-0402_R 130.1,81.643 r270 top
R28 "33R" LC-0402_R 109.405,69.2 r90 top
R29 "33R" LC-0402_R 107.373,69.193 r90 top
R30 "10K" LC-0402_R 107.975,71.044 r180 top
R31 "330R" LC-0402_R 138.633,94.132 r90 top
R32 "330R" LC-0402_R 139.802,94.132 r90 top
R33 "1.5K" LC-0402_R 128.041,75.812 r90 top
R34 "1.5K" LC-0402_R 128.931,81.643 r90 top
R35 "4.7K" LC-0402_R 131.243,81.643 r90 top
R36 "4.7K" LC-0402_R 125.146,90.754 r0 top
R37 "33R" LC-0402_R 109.086,72.822 r0 top
R38 "4.7K" LC-0402_R 125.147,84.869 r0 top
R39 "4.7K" LC-0402_R 125.147,88.298 r180 top
R40 "4.7K" LC-0402_R 132.386,81.643 r90 top
R41 "4.7K" LC-0402_R 125.147,89.441 r180 top
R42 "33R" LC-0402_R 127.229,71.78 r0 top
R43 "4.7K" LC-0402_R 125.147,87.155 r180 top
R44 "8.06K" LC-0402_R 136.195,71.933 r0 top
R45 "4.7K" LC-0402_R 125.147,86.012 r180 top
R46 "4.7K" LC-0402_R 133.554,81.643 r90 top
R47 "20K" LC-0402_R 112.827,75.565 r180 bottom
R48 "1K" LC-0402_R 94.793,111.887 r90 top
R49 "20K" LC-0402_R 96.698,115.037 r0 top
R50 "20K" LC-0402_R 96.698,112.547 r0 top
R51 "20K" LC-0402_R 108.458,112.471 r180 top
R52 "20K" LC-0402_R 108.465,113.792 r180 top
R53 "20K" LC-0402_R 94.818,114.503 r270 top
R54 "10K" LC-0402_R 108.458,115.037 r180 top
R55 "4.7K" LC-0402_R 88.29,71.552 r270 bottom
R56 "20K" LC-0402_R 115.011,75.565 r180 bottom
R57 "4.7K" LC-0402_R 95.885,74.016 r0 bottom
R58 "33R" LC-0402_R 96.698,113.767 r180 top
R59 "470R" LC-0402_R 108.458,111.176 r0 top
R60 "470R" LC-0402_R 121.031,71.12 r0 top
R61 "470R" LC-0402_R 86.182,74.244 r0 top
R62 "4.7K" LC-0402_R 126.289,64.491 r180 top
R63 "4.7K" LC-0402_R 136.899,51.816 r180 bottom
R64 "0R" LC-0402_R 138.735,63.436 r90 top
R65 "10K" LC-0402_R 121.031,72.288 r0 top
R66 "1K" LC-0402_R 136.195,70.79 r180 top
R67 "0R" LC-0402_R 131.928,63.398 r270 top
R68 "100K" LC-0402_R 137.566,63.431 r90 top
R69 "10K" LC-0402_R 135.179,66.37 r180 top
R70 "330R" LC-0402_R 126.473,45.212 r180 top
R71 "10K" LC-0402_R 126.467,44.069 r0 top
R72 "40.2R" LC-0402_R 118.999,62.509 r180 top
R73 "1R" LC-0402_R 84.411,52.934 r0 top
R74 "1R" LC-0402_R 84.379,57.38 r0 top
R75 "14.3K" LC-0402_R 95.783,50.546 r270 bottom
RESET "SW-PB" 开关 120.244,76.352 r270 top
RP1 "10K" LC-0402_R 109.913,59.588 r0 top
RP2 "20K" LC-0402_R 109.919,60.731 r180 top
RX1 "JCCEM001" CNSMARAL687W375H171 93.32,29.197 r270 top
RX2 "JCCEM001" CNSMARAL687W375H171 74.422,29.197 r270 top
RX4 "0R" LC-0402_R 93.066,53.264 r180 bottom
RX5 "0R" LC-0402_R 92.786,47.65 r0 bottom
RX6 "0R" LC-0603_L 119.169,51.867 r0 top
RX7 "0R" LC-0603_L 82.779,60.096 r90 bottom
RX8 "0R" LC-0603_L 65.202,60.223 r90 top
RX10 "0R" LC-0402_R 89.941,63.957 r90 bottom
RX13 "0R" LC-0603_L 119.177,47.625 r0 bottom
RX14 "0R" LC-0603_L 123.393,41.529 r90 bottom
RX15 "0R" LC-0603_L 140.691,41.402 r90 top
RX22 "0R" LC-0402_R 92.1,58.141 r270 bottom
T1 "TCM1-63AX+" TSML150W160H160 97.511,41.58 r180 top
T2 "TCM1-63AX+" TSML150W160H160 92.227,41.542 r180 top
T3 "TCM1-63AX+" TSML150W160H160 112.141,46.863 r180 top
T4 "TCM1-63AX+" TSML150W160H160 106.401,44.272 r180 top
tf1 "TF-SD" TF 138.735,51.791 r0 top
TU1 "TPS2051BDBVR" TPS2051BDBVR 134.823,62.992 r270 top
TX1 "JCCEM001" CNSMARAL687W375H171 132.779,29.121 r270 top
TX2 "JCCEM001" CNSMARAL687W375H171 113.894,29.197 r270 top
U1 "XC7Z010-CLG400" CLG400-0.8 97.81,69.92 r270 top locked
U2 "MT41J64M16JT-187EG" FBGA96 109.299,103.215 r270 top locked
U3 "RTL8211E-VB-CG" LC-QFN-48_6x6x04P 131.176,87.718 r180 top
U4 "USB3320C" LC-QFN-32_5x5x05P 131.674,70.053 r270 top
U5 "AD9363" AD936X 90.933,52.414 r90 top locked
U6 "TLV62130" TLV62130RGT 71.12,73.889 r90 top
U7 "TLV62130" TLV62130RGT 71.095,64.645 r90 top
U8 "TLV62130" TLV62130RGT 71.206,91.663 r90 top
U9 "TLV62130" TLV62130RGT 71.158,82.829 r90 top
U11 "TPS7A8101" TPS7A8101 70.942,53.848 r270 top
U12 "TPS7A8101" TPS7A8101 71.013,43.943 r270 top
U13 "TCM811TE" TCM811TERCTR 116.223,75.946 r270 top
UP1 "AP3419" AP3419 110.429,56.609 r270 top
USD1 "TXS02612RTWR" TXS02612RTWR 122.718,62.173 r270 top
USR_BTN "SW-PB" 开关 123.723,76.505 r90 top
USR_LED "LED" D0402 123.038,71.53 r270 top
X1 "25M" LC-SMD-5032_2P 139.675,88.087 r270 top
X2 "33.333MHz" OSC-SMD_4P-L3.2-W2.5-BL 111.684,72.914 r90 top
X3 "24M" LC-SMD-5032_2P 132.914,75.794 r0 top
X4 "40MHz" OSC-SMD_4P-L3.2-W2.5-BL 100.228,57.862 r180 top

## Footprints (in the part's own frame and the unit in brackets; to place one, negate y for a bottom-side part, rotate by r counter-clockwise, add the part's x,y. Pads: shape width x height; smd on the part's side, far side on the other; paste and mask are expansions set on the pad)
AD936X [mil]
  round 14 smd: A1(-137.01,164.51) A2(-105.51,164.51) A3(-74.02,164.51) A4(-42.52,164.51) A5(-11.02,164.51) A6(20.47,164.51) A7(51.97,164.51) A8(83.46,164.51) A9(114.96,164.51) A10(146.46,164.51) A11(177.95,164.51) A12(209.45,164.51) B1(-137.01,133.01) B2(-105.51,133.01) B3(-74.02,133.01) B4(-42.52,133.01) B5(-11.02,133.01) B6(20.47,133.01) B7(51.97,133.01) B8(83.46,133.01) B9(114.96,133.01) B10(146.46,133.01) B11(177.95,133.01) B12(209.45,133.01) C1(-137.01,101.52) C2(-105.51,101.52) C3(-74.02,101.52) C4(-42.52,101.52) C5(-11.02,101.52) C6(20.47,101.52) C7(51.97,101.52) C8(83.46,101.52) C9(114.96,101.52) C10(146.46,101.52) C11(177.95,101.52) C12(209.45,101.52) D1(-137.01,70.02) D2(-105.51,70.02) D3(-74.02,70.02) D4(-42.52,70.02) D5(-11.02,70.02) D6(20.47,70.02) D7(51.97,70.02) D8(83.46,70.02) D9(114.96,70.02) D10(146.46,70.02) D11(177.95,70.02) D12(209.45,70.02) E1(-137.01,38.52) E2(-105.51,38.52) E3(-74.02,38.52) E4(-42.52,38.52) E5(-11.02,38.52) E6(20.47,38.52) E7(51.97,38.52) E8(83.46,38.52) E9(114.96,38.52) E10(146.46,38.52) E11(177.95,38.52) E12(209.45,38.52) F1(-137.01,7.03) F2(-105.51,7.03) F3(-74.02,7.03) F4(-42.52,7.03) F5(-11.02,7.03) F6(20.47,7.03) F7(51.97,7.03) F8(83.46,7.03) F9(114.96,7.03) F10(146.46,7.03) F11(177.95,7.03) F12(209.45,7.03) G1(-137.01,-24.47) G2(-105.51,-24.47) G3(-74.02,-24.47) G4(-42.52,-24.47) G5(-11.02,-24.47) G6(20.47,-24.47) G7(51.97,-24.47) G8(83.46,-24.47) G9(114.96,-24.47) G10(146.46,-24.47) G11(177.95,-24.47) G12(209.45,-24.47) H1(-137.01,-55.96) H2(-105.51,-55.96) H3(-74.02,-55.96) H4(-42.52,-55.96) H5(-11.02,-55.96) H6(20.47,-55.96) H7(51.97,-55.96) H8(83.46,-55.96) H9(114.96,-55.96) H10(146.46,-55.96) H11(177.95,-55.96) H12(209.45,-55.96) J1(-137.01,-87.46) J2(-105.51,-87.46) J3(-74.02,-87.46) J4(-42.52,-87.46) J5(-11.02,-87.46) J6(20.47,-87.46) J7(51.97,-87.46) J8(83.46,-87.46) J9(114.96,-87.46) J10(146.46,-87.46) J11(177.95,-87.46) J12(209.45,-87.46) K1(-137.01,-118.96) K2(-105.51,-118.96) K3(-74.02,-118.96) K4(-42.52,-118.96) K5(-11.02,-118.96) K6(20.47,-118.96) K7(51.97,-118.96) K8(83.46,-118.96) K9(114.96,-118.96) K10(146.46,-118.96) K11(177.95,-118.96) K12(209.45,-118.96) L1(-137.01,-150.45) L2(-105.51,-150.45) L3(-74.02,-150.45) L4(-42.52,-150.45) L5(-11.02,-150.45) L6(20.47,-150.45) L7(51.97,-150.45) L8(83.46,-150.45) L9(114.96,-150.45) L10(146.46,-150.45) L11(177.95,-150.45) L12(209.45,-150.45) M1(-137.01,-181.95) M2(-105.51,-181.95) M3(-74.02,-181.95) M4(-42.52,-181.95) M5(-11.02,-181.95) M6(20.47,-181.95) M7(51.97,-181.95) M8(83.46,-181.95) M9(114.96,-181.95) M10(146.46,-181.95) M11(177.95,-181.95) M12(209.45,-181.95)
  silkscreen extent -161,-206 233,188
AP3419 [mm]
  rect 1x0.55 smd: 1(1.268,-0.95) 2(1.268,0) 3(1.268,0.95) 4(-1.532,0.95) 5(-1.532,0) 6(-1.532,-0.95)
  silkscreen extent -1.03,-1.78 1.39,1.55
CLG400-0.8 [mm]
  round 0.35 smd: A1(-7.6,7.6) A2(-6.8,7.6) A3(-6,7.6) A4(-5.2,7.6) A5(-4.4,7.6) A6(-3.6,7.6) A7(-2.8,7.6) A8(-2,7.6) A9(-1.2,7.6) A10(-0.4,7.6) A11(0.4,7.6) A12(1.2,7.6) A13(2,7.6) A14(2.8,7.6) A15(3.6,7.6) A16(4.4,7.6) A17(5.2,7.6) A18(6,7.6) A19(6.8,7.6) A20(7.6,7.6) B1(-7.6,6.8) B2(-6.8,6.8) B3(-6,6.8) B4(-5.2,6.8) B5(-4.4,6.8) B6(-3.6,6.8) B7(-2.8,6.8) B8(-2,6.8) B9(-1.2,6.8) B10(-0.4,6.8) B11(0.4,6.8) B12(1.2,6.8) B13(2,6.8) B14(2.8,6.8) B15(3.6,6.8) B16(4.4,6.8) B17(5.2,6.8) B18(6,6.8) B19(6.8,6.8) B20(7.6,6.8) C1(-7.6,6) C2(-6.8,6) C3(-6,6) C4(-5.2,6) C5(-4.4,6) C6(-3.6,6) C7(-2.8,6) C8(-2,6) C9(-1.2,6) C10(-0.4,6) C11(0.4,6) C12(1.2,6) C13(2,6) C14(2.8,6) C15(3.6,6) C16(4.4,6) C17(5.2,6) C18(6,6) C19(6.8,6) C20(7.6,6) D1(-7.6,5.2) D2(-6.8,5.2) D3(-6,5.2) D4(-5.2,5.2) D5(-4.4,5.2) D6(-3.6,5.2) D7(-2.8,5.2) D8(-2,5.2) D9(-1.2,5.2) D10(-0.4,5.2) D11(0.4,5.2) D12(1.2,5.2) D13(2,5.2) D14(2.8,5.2) D15(3.6,5.2) D16(4.4,5.2) D17(5.2,5.2) D18(6,5.2) D19(6.8,5.2) D20(7.6,5.2) E1(-7.6,4.4) E2(-6.8,4.4) E3(-6,4.4) E4(-5.2,4.4) E5(-4.4,4.4) E6(-3.6,4.4) E7(-2.8,4.4) E8(-2,4.4) E9(-1.2,4.4) E10(-0.4,4.4) E11(0.4,4.4) E12(1.2,4.4) E13(2,4.4) E14(2.8,4.4) E15(3.6,4.4) E16(4.4,4.4) E17(5.2,4.4) E18(6,4.4) E19(6.8,4.4) E20(7.6,4.4) F1(-7.6,3.6) F2(-6.8,3.6) F3(-6,3.6) F4(-5.2,3.6) F5(-4.4,3.6) F6(-3.6,3.6) F7(-2.8,3.6) F8(-2,3.6) F9(-1.2,3.6) F10(-0.4,3.6) F11(0.4,3.6) F12(1.2,3.6) F13(2,3.6) F14(2.8,3.6) F15(3.6,3.6) F16(4.4,3.6) F17(5.2,3.6) F18(6,3.6) F19(6.8,3.6) F20(7.6,3.6) G1(-7.6,2.8) G2(-6.8,2.8) G3(-6,2.8) G4(-5.2,2.8) G5(-4.4,2.8) G6(-3.6,2.8) G7(-2.8,2.8) G8(-2,2.8) G9(-1.2,2.8) G10(-0.4,2.8) G11(0.4,2.8) G12(1.2,2.8) G13(2,2.8) G14(2.8,2.8) G15(3.6,2.8) G16(4.4,2.8) G17(5.2,2.8) G18(6,2.8) G19(6.8,2.8) G20(7.6,2.8) H1(-7.6,2) H2(-6.8,2) H3(-6,2) H4(-5.2,2) H5(-4.4,2) H6(-3.6,2) H7(-2.8,2) H8(-2,2) H9(-1.2,2) H10(-0.4,2) H11(0.4,2) H12(1.2,2) H13(2,2) H14(2.8,2) H15(3.6,2) H16(4.4,2) H17(5.2,2) H18(6,2) H19(6.8,2) H20(7.6,2) J1(-7.6,1.2) J2(-6.8,1.2) J3(-6,1.2) J4(-5.2,1.2) J5(-4.4,1.2) J6(-3.6,1.2) J7(-2.8,1.2) J8(-2,1.2) J9(-1.2,1.2) J10(-0.4,1.2) J11(0.4,1.2) J12(1.2,1.2) J13(2,1.2) J14(2.8,1.2) J15(3.6,1.2) J16(4.4,1.2) J17(5.2,1.2) J18(6,1.2) J19(6.8,1.2) J20(7.6,1.2) K1(-7.6,0.4) K2(-6.8,0.4) K3(-6,0.4) K4(-5.2,0.4) K5(-4.4,0.4) K6(-3.6,0.4) K7(-2.8,0.4) K8(-2,0.4) K9(-1.2,0.4) K10(-0.4,0.4) K11(0.4,0.4) K12(1.2,0.4) K13(2,0.4) K14(2.8,0.4) K15(3.6,0.4) K16(4.4,0.4) K17(5.2,0.4) K18(6,0.4) K19(6.8,0.4) K20(7.6,0.4) L1(-7.6,-0.4) L2(-6.8,-0.4) L3(-6,-0.4) L4(-5.2,-0.4) L5(-4.4,-0.4) L6(-3.6,-0.4) L7(-2.8,-0.4) L8(-2,-0.4) L9(-1.2,-0.4) L10(-0.4,-0.4) L11(0.4,-0.4) L12(1.2,-0.4) L13(2,-0.4) L14(2.8,-0.4) L15(3.6,-0.4) L16(4.4,-0.4) L17(5.2,-0.4) L18(6,-0.4) L19(6.8,-0.4) L20(7.6,-0.4) M1(-7.6,-1.2) M2(-6.8,-1.2) M3(-6,-1.2) M4(-5.2,-1.2) M5(-4.4,-1.2) M6(-3.6,-1.2) M7(-2.8,-1.2) M8(-2,-1.2) M9(-1.2,-1.2) M10(-0.4,-1.2) M11(0.4,-1.2) M12(1.2,-1.2) M13(2,-1.2) M14(2.8,-1.2) M15(3.6,-1.2) M16(4.4,-1.2) M17(5.2,-1.2) M18(6,-1.2) M19(6.8,-1.2) M20(7.6,-1.2) N1(-7.6,-2) N2(-6.8,-2) N3(-6,-2) N4(-5.2,-2) N5(-4.4,-2) N6(-3.6,-2) N7(-2.8,-2) N8(-2,-2) N9(-1.2,-2) N10(-0.4,-2) N11(0.4,-2) N12(1.2,-2) N13(2,-2) N14(2.8,-2) N15(3.6,-2) N16(4.4,-2) N17(5.2,-2) N18(6,-2) N19(6.8,-2) N20(7.6,-2) P1(-7.6,-2.8) P2(-6.8,-2.8) P3(-6,-2.8) P4(-5.2,-2.8) P5(-4.4,-2.8) P6(-3.6,-2.8) P7(-2.8,-2.8) P8(-2,-2.8) P9(-1.2,-2.8) P10(-0.4,-2.8) P11(0.4,-2.8) P12(1.2,-2.8) P13(2,-2.8) P14(2.8,-2.8) P15(3.6,-2.8) P16(4.4,-2.8) P17(5.2,-2.8) P18(6,-2.8) P19(6.8,-2.8) P20(7.6,-2.8) R1(-7.6,-3.6) R2(-6.8,-3.6) R3(-6,-3.6) R4(-5.2,-3.6) R5(-4.4,-3.6) R6(-3.6,-3.6) R7(-2.8,-3.6) R8(-2,-3.6) R9(-1.2,-3.6) R10(-0.4,-3.6) R11(0.4,-3.6) R12(1.2,-3.6) R13(2,-3.6) R14(2.8,-3.6) R15(3.6,-3.6) R16(4.4,-3.6) R17(5.2,-3.6) R18(6,-3.6) R19(6.8,-3.6) R20(7.6,-3.6) T1(-7.6,-4.4) T2(-6.8,-4.4) T3(-6,-4.4) T4(-5.2,-4.4) T5(-4.4,-4.4) T6(-3.6,-4.4) T7(-2.8,-4.4) T8(-2,-4.4) T9(-1.2,-4.4) T10(-0.4,-4.4) T11(0.4,-4.4) T12(1.2,-4.4) T13(2,-4.4) T14(2.8,-4.4) T15(3.6,-4.4) T16(4.4,-4.4) T17(5.2,-4.4) T18(6,-4.4) T19(6.8,-4.4) T20(7.6,-4.4) U1(-7.6,-5.2) U2(-6.8,-5.2) U3(-6,-5.2) U4(-5.2,-5.2) U5(-4.4,-5.2) U6(-3.6,-5.2) U7(-2.8,-5.2) U8(-2,-5.2) U9(-1.2,-5.2) U10(-0.4,-5.2) U11(0.4,-5.2) U12(1.2,-5.2) U13(2,-5.2) U14(2.8,-5.2) U15(3.6,-5.2) U16(4.4,-5.2) U17(5.2,-5.2) U18(6,-5.2) U19(6.8,-5.2) U20(7.6,-5.2) V1(-7.6,-6) V2(-6.8,-6) V3(-6,-6) V4(-5.2,-6) V5(-4.4,-6) V6(-3.6,-6) V7(-2.8,-6) V8(-2,-6) V9(-1.2,-6) V10(-0.4,-6) V11(0.4,-6) V12(1.2,-6) V13(2,-6) V14(2.8,-6) V15(3.6,-6) V16(4.4,-6) V17(5.2,-6) V18(6,-6) V19(6.8,-6) V20(7.6,-6) W1(-7.6,-6.8) W2(-6.8,-6.8) W3(-6,-6.8) W4(-5.2,-6.8) W5(-4.4,-6.8) W6(-3.6,-6.8) W7(-2.8,-6.8) W8(-2,-6.8) W9(-1.2,-6.8) W10(-0.4,-6.8) W11(0.4,-6.8) W12(1.2,-6.8) W13(2,-6.8) W14(2.8,-6.8) W15(3.6,-6.8) W16(4.4,-6.8) W17(5.2,-6.8) W18(6,-6.8) W19(6.8,-6.8) W20(7.6,-6.8) Y1(-7.6,-7.6) Y2(-6.8,-7.6) Y3(-6,-7.6) Y4(-5.2,-7.6) Y5(-4.4,-7.6) Y6(-3.6,-7.6) Y7(-2.8,-7.6) Y8(-2,-7.6) Y9(-1.2,-7.6) Y10(-0.4,-7.6) Y11(0.4,-7.6) Y12(1.2,-7.6) Y13(2,-7.6) Y14(2.8,-7.6) Y15(3.6,-7.6) Y16(4.4,-7.6) Y17(5.2,-7.6) Y18(6,-7.6) Y19(6.8,-7.6) Y20(7.6,-7.6)
  silkscreen extent -9.02,-8.5 8.5,8.5
CNSMARAL687W375H171 [mil]
  rect 200x19 smd: 1(2.5,0)
  rect 200x95 smd: 2(2.5,172.5) 4(2.5,-172.5)
  rect 200x95 smd far side: 3(2.5,172.5) 5(2.5,-172.5)
  silkscreen extent -113,-235 113,235
D0402 [mm]
  rect 0.51x0.51 smd: 1(-0.41,0) 2(0.41,0)
  silkscreen extent -0.91,-0.5 0.91,0.5
FBGA96 [mm]
  round 0.4 smd: A1(2.504,-0.906) A2(3.304,-0.906) A3(4.104,-0.906) A7(7.304,-0.906) A8(8.104,-0.906) A9(8.904,-0.906) B1(2.504,-1.706) B2(3.304,-1.706) B3(4.104,-1.706) B7(7.304,-1.706) B8(8.104,-1.706) B9(8.904,-1.706) C1(2.504,-2.506) C2(3.304,-2.506) C3(4.104,-2.506) C7(7.304,-2.506) C8(8.104,-2.506) C9(8.904,-2.506) D1(2.504,-3.306) D2(3.304,-3.306) D3(4.104,-3.306) D7(7.304,-3.306) D8(8.104,-3.306) D9(8.904,-3.306) E1(2.504,-4.106) E2(3.304,-4.106) E3(4.104,-4.106) E7(7.304,-4.106) E8(8.104,-4.106) E9(8.904,-4.106) F1(2.504,-4.906) F2(3.304,-4.906) F3(4.104,-4.906) F7(7.304,-4.906) F8(8.104,-4.906) F9(8.904,-4.906) G1(2.504,-5.706) G2(3.304,-5.706) G3(4.104,-5.706) G7(7.304,-5.706) G8(8.104,-5.706) G9(8.904,-5.706) H1(2.504,-6.506) H2(3.304,-6.506) H3(4.104,-6.506) H7(7.304,-6.506) H8(8.104,-6.506) H9(8.904,-6.506) J1(2.504,-7.306) J2(3.304,-7.306) J3(4.104,-7.306) J7(7.304,-7.306) J8(8.104,-7.306) J9(8.904,-7.306) K1(2.504,-8.106) K2(3.304,-8.106) K3(4.104,-8.106) K7(7.304,-8.106) K8(8.104,-8.106) K9(8.904,-8.106) L1(2.504,-8.906) L2(3.304,-8.906) L3(4.104,-8.906) L7(7.304,-8.906) L8(8.104,-8.906) L9(8.904,-8.906) M1(2.504,-9.706) M2(3.304,-9.706) M3(4.104,-9.706) M7(7.304,-9.706) M8(8.104,-9.706) M9(8.904,-9.706) N1(2.504,-10.506) N2(3.304,-10.506) N3(4.104,-10.506) N7(7.304,-10.506) N8(8.104,-10.506) N9(8.904,-10.506) P1(2.504,-11.306) P2(3.304,-11.306) P3(4.104,-11.306) P7(7.304,-11.306) P8(8.104,-11.306) P9(8.904,-11.306) R1(2.504,-12.106) R2(3.304,-12.106) R3(4.104,-12.106) R7(7.304,-12.106) R8(8.104,-12.106) R9(8.904,-12.106) T1(2.504,-12.906) T2(3.304,-12.906) T3(4.104,-12.906) T7(7.304,-12.906) T8(8.104,-12.906) T9(8.904,-12.906)
  silkscreen extent -0.2,-14.01 10.8,0.2
HDR2X12_CEN [mm] "Connector; Header; 12x2 Position"
  rect 1.5x1.5 hole 0.9: 1(0,0)
  round 1.5 hole 0.9: 2(2.54,0) 3(5.08,0) 4(7.62,0) 5(10.16,0) 6(12.7,0) 7(15.24,0) 8(17.78,0) 9(20.32,0) 10(22.86,0) 11(25.4,0) 12(27.94,0) 13(0,2.54) 14(2.54,2.54) 15(5.08,2.54) 16(7.62,2.54) 17(10.16,2.54) 18(12.7,2.54) 19(15.24,2.54) 20(17.78,2.54) 21(20.32,2.54) 22(22.86,2.54) 23(25.4,2.54) 24(27.94,2.54)
  silkscreen extent -1.27,-1.27 29.21,3.81
HR911130C [mil]
  round 66.93 hole 43.31: 11(260,272.62) 12(160,272.62) 13(-160,272.62) 14(-260,272.62)
  rect 60x60 hole 35.83: P1(229.63,-272.62)
  round 60 hole 35.83: P2(179.1,-172.38) P3(125.2,-272.38) P4(79.1,-172.38) P5(25.2,-272.38) P6(-20.9,-172.38) P7(-74.8,-272.38) P8(-120.9,-172.38) P9(-174.8,-272.38) P10(-220.9,-172.38)
  round 85 hole 65: SHIELD0(-315,-42.48) SHIELD1(315,-42.48)
  round 127.95 hole 127.95 unplated: ""(-224.4,77.62) ""(224.4,77.62)
  silkscreen extent -315,-347 315,503
L1008 [mil]
  rect 33.5x98.4 smd: 1(-39.92,0) 2(40.08,0)
  silkscreen extent -31,-39 31,39
LC-0402_C [mm]
  rect 0.6x0.65 smd mask+0.051: 1(-0.425,0) 2(0.425,0)
  silkscreen extent -0.97,-0.58 0.98,0.58, body extent -0.48,-0.3 0.52,0.3, height 0.2
LC-0402_R [mm]
  rect 0.6x0.65 smd mask+0.051: 1(-0.425,0) 2(0.425,0)
  silkscreen extent -0.97,-0.58 0.97,0.58, body extent -0.57,-0.27 0.57,0.28, height 0.41
LC-0603_L [mm]
  oval 0.93x0.98 smd: 1(-0.77,0) 2(0.77,0)
  silkscreen extent -1.53,-0.79 1.54,0.79, body extent -0.8,-0.41 0.8,0.41, height 0.46
LC-0805_C [mm]
  rect 1.16x1.47 smd: 1(-0.89,0) 2(0.89,0)
  silkscreen extent -1.77,-1.04 1.77,1.04
LC-QFN-32_5x5x05P [mm]
  rect 3.5x3.5 smd paste-1.75 mask+0.051: 0(0,0)
  oval 0.28x0.9 smd mask+0.051: 1(-1.75,-2.55) 2(-1.25,-2.55) 3(-0.75,-2.55) 4(-0.25,-2.55) 5(0.25,-2.55) 6(0.75,-2.55) 7(1.25,-2.55) 8(1.75,-2.55) 17(1.75,2.55) 18(1.25,2.55) 19(0.75,2.55) 20(0.25,2.55) 21(-0.25,2.55) 22(-0.75,2.55) 23(-1.25,2.55) 24(-1.75,2.55)
  oval 0.9x0.28 smd mask+0.051: 9(2.55,-1.75) 10(2.55,-1.25) 11(2.55,-0.75) 12(2.55,-0.25) 13(2.55,0.25) 14(2.55,0.75) 15(2.55,1.25) 16(2.55,1.75) 25(-2.55,1.75) 26(-2.55,1.25) 27(-2.55,0.75) 28(-2.55,0.25) 29(-2.55,-0.25) 30(-2.55,-0.75) 31(-2.55,-1.25) 32(-2.55,-1.75)
  silkscreen extent -2.7,-3.35 2.7,2.7
LC-QFN-48_6x6x04P [mm]
  rect 4.2x4.2 smd mask+0.051: 0(0,0)
  oval 0.22x1 smd mask+0.051: 1(-2.2,-2.9) 2(-1.8,-2.9) 3(-1.4,-2.9) 4(-1,-2.9) 5(-0.6,-2.9) 6(-0.2,-2.9) 7(0.2,-2.9) 8(0.6,-2.9) 9(1,-2.9) 10(1.4,-2.9) 11(1.8,-2.9) 12(2.2,-2.9) 25(2.2,2.9) 26(1.8,2.9) 27(1.4,2.9) 28(1,2.9) 29(0.6,2.9) 30(0.2,2.9) 31(-0.2,2.9) 32(-0.6,2.9) 33(-1,2.9) 34(-1.4,2.9) 35(-1.8,2.9) 36(-2.2,2.9)
  oval 1x0.22 smd mask+0.051: 13(2.9,-2.2) 14(2.9,-1.8) 15(2.9,-1.4) 16(2.9,-1) 17(2.9,-0.6) 18(2.9,-0.2) 19(2.9,0.2) 20(2.9,0.6) 21(2.9,1) 22(2.9,1.4) 23(2.9,1.8) 24(2.9,2.2) 37(-2.9,2.2) 38(-2.9,1.8) 39(-2.9,1.4) 40(-2.9,1) 41(-2.9,0.6) 42(-2.9,0.2) 43(-2.9,-0.2) 44(-2.9,-0.6) 45(-2.9,-1) 46(-2.9,-1.4) 47(-2.9,-1.8) 48(-2.9,-2.2)
  silkscreen extent -3.2,-3.85 3.2,3.2
LC-SMD-5032_2P [mm]
  rect 1.7x2.4 smd: 1(-1.96,0.001) 2(1.96,-0.001)
  silkscreen extent -2.51,-1.67 2.49,1.55
"micro usb" [mm]
  rect 0.4x2 smd: 1(1.145,0.066) 2(1.795,0.066) 3(2.445,0.066) 4(3.095,0.066) 5(3.745,0.066)
  round 1.3 hole 0.7: 6(4.87,0.074) 9(0.02,0.074)
  oval 1.3x2.199 hole 0.7 slot 1.5 at 90 deg: 7(6.045,-2.597) 8(-1.155,-2.597)
  silkscreen extent -1.55,-5.33 6.45,0.42
NMOS [mil]
  rect 36x36 smd: 1(80,-39) 2(80,36)
  rect 50x36 smd: 3(0,-1)
  silkscreen extent -5,-59 85,56
OSC-SMD_4P-L3.2-W2.5-BL [mm]
  rect 0.5x0.5 smd: 1(-2.454,-1.371)
  rect 1.4x1.15 smd: 2(-0.254,-1.371) 3(-0.254,0.229) 4(-2.454,0.229)
  Top Layer region: -3.154,-0.796 -2.116,-0.796 -1.754,-1.175 -1.754,-1.946 -3.154,-1.946
  silkscreen extent -3.45,-2.92 0.75,1.13
TCM811TERCTR [mil]
  rect 12x30 smd: 1(-36,-41.3) 2(39,-41.3) 3(39,41.3) 4(-36,41.3)
  silkscreen extent -57,-81 57,66
TF [mm]
  rect 1.4x1.6 smd: 0(-4.55,6.85)
  rect 1.6x0.7 smd: 1(-5.05,2.25) 2(-5.05,1.15) 3(-5.05,0.05) 4(-5.05,-1.05) 5(-5.05,-2.15) 6(-5.05,-3.25) 7(-5.05,-4.35) 8(-5.05,-5.45) 9(-5.05,-6.55)
  rect 1.4x1.2 smd: 10(-4.55,-7.75)
  rect 2.2x1.2 smd: 11(5.05,-7.75) 12(5.05,7.75)
  silkscreen extent -4.06,-7.29 9.47,7.15
TLV62130RGT [mil]
  oval 11x33.5 smd: 1(-29.5,-58.6) 2(-9.8,-58.6) 3(9.8,-58.6) 4(29.5,-58.6) 9(29.5,57.6) 10(9.8,57.6) 11(-9.8,57.6) 12(-29.5,57.6)
  oval 33.5x11 smd: 5(58.1,-30) 6(58.1,-10.3) 7(58.1,9.3) 8(58.1,29) 13(-58.1,29) 14(-58.1,9.3) 15(-58.1,-10.3) 16(-58.1,-30)
  rect 66.9x66.9 smd: 20(0,-0.5)
  silkscreen extent -59,-94 59,59
TPS7A8101 [mm]
  rect 1.5x2.8 smd: 0(0,0)
  rect 0.6x0.3 smd: 1(-1.5,0.975) 2(-1.5,0.325) 3(-1.5,-0.325) 4(-1.5,-0.975) 5(1.5,-0.975) 6(1.5,-0.325) 7(1.5,0.325) 8(1.5,0.975)
  silkscreen extent -1.6,-1.6 1.6,1.6, body extent -1.5,-1.5 1.5,1.5, height 0.6
TPS2051BDBVR [mm]
  rect 1x0.55 smd: 1(1.087,-0.95) 2(1.087,0) 3(1.087,0.95) 4(-1.913,0.95) 5(-1.913,-0.95)
  silkscreen extent -1.31,-1.78 1.24,1.55
TSML150W160H160 [mil]
  rect 30x65 smd: 1(-50,62.51) 2(0,62.51) 3(50,62.51) 4(50,-62.49) 5(0,-62.49) 6(-50,-62.49)
  silkscreen extent -130,-110 90,110, body extent -90,-110 90,110, height 150
TXS02612RTWR [mil]
  rect 33.4x11.8 smd: 1(-79.76,52.7) 2(-79.76,33) 3(-79.76,13.3) 4(-79.76,-6.4) 5(-79.76,-26) 6(-79.76,-45.7) 13(73.74,-45.7) 14(73.74,-26) 15(73.74,-6.4) 16(73.74,13.3) 17(73.74,33) 18(73.74,52.7)
  rect 11.8x33.4 smd: 7(-52.16,-73.3) 8(-32.56,-73.3) 9(-12.86,-73.3) 10(6.84,-73.3) 11(26.55,-73.3) 12(46.24,-73.3) 19(46.24,80.3) 20(26.55,80.3) 21(6.84,80.3) 22(-12.86,80.3) 23(-32.56,80.3) 24(-52.16,80.3)
  rect 98.4x98.4 smd: 25(-2.76,3.7)
  silkscreen extent -110,-81 82,88
W25Q256 [mm]
  rect 0.5x1 smd: 1(-1.92,-3.8) 2(-0.64,-3.8) 3(0.64,-3.8) 4(1.92,-3.8) 5(1.92,3.8) 6(0.64,3.8) 7(-0.64,3.8) 8(-1.92,3.8)
  rect 4.3x3.4 smd: 9(0,0)
  silkscreen extent -3,-4.7 3,4
开关 [mm]
  rect 1.2x2 smd: 1(-2.321,-0.024) 2(2.179,-0.024)
  silkscreen extent -2.07,-1.52 1.93,1.48

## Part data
C1 C159 C160 C161 C187 C188 C189 C190 C191 C192 C193: library part CAP, "Capacitor"
C2 C3 C4 C5 C6 C7 C8 C9 C10 C11 C12 C13 C17 C18 C19 C20 C21 C22 C23 C24 C25 C26 C27 C28 C33 C34 C35 C36 C37 C38 C39 C49 C50 C51 C52 C53 C57 C61 C62 C67 C68 C69 C70 C71 C72 C73 C74 C75 C76 C77 C78 C80 C81 C82 C83 C85 C86 C87 C89 C90 C91 C96 C98 C99 C100 C101 C102 C103 C104 C105 C106 C107 C108 C148 C149 C181 C182 C183: library part CAP_3, "Capacitor"
C16 C29 C30 C31 C32 C40 C47 C48 C117 C118 C122 C123 C145 C146 C150 C151 C152 C166 C170 C172 C174 C175 C177 CP1 CP3: library part CAP_1, "Capacitor"
C58 C59 C60 C63 C109 C110 C111 C112 C113 C114 C115 C116 C119 C120 C121 C124 C125 C126 C127 C128 C129 C130 C131 C132 C133 C134 C135 C136 C137 C138 C139 C141 C142 C143 C144 CP2: library part CAP_2, "Capacitor"
DONE USR_LED: library part LED0, "Typical INFRARED GaAs LED"
L1 L2 L3 L4 L6: library part INDUCTANCE_1, "Inductance"
L5 L7 L8 L9 LP1: library part INDUCTANCE, "Inductance"
LG1: BOM_Manufacturer=HANRUN
P2: "Header, 12-Pin, Dual row"
Q1 Q2: PSpiceTemplate="X^@REFDES %d %g %s @MODEL"
R1 R2 R3 R4 R5 R6 R7 R8 R9 R10 R11 R12 R13 R14 R15 R16 R17 R18 R19 R20 R21 R22 R23 R24 R25 R26 R27 R28 R29 R30 R31 R32 R33 R34 R35 R36 R37 R38 R39 R40 R41 R42 R43 R44 R45 R46 R47 R48 R49 R50 R51 R52 R53 R54 R55 R56 R57 R58 R59 R60 R61 R62 R63 R64 R65 R66 R67 R68 R69 R70 R71 R72: library part RES, "Resistor"
R73 R74 R75 RP1 RP2 RX4 RX5 RX6 RX7 RX8 RX10 RX13 RX14 RX15 RX22: library part RES_1, "Resistor"
RESET USR_BTN: "Switch"
U2: library part DDR3
X1 X3: library part XTAL-2, "Crystal"
X2 X4: library part XTAL-4, "Oscillator"

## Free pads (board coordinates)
  round 6 hole 3: 0(63.221,30.505) 0(63.221,30.505) 0(63.221,30.505) 0(63.221,114.148) 0(63.221,114.148) 0(63.221,114.148) 0(144.323,30.505) 0(144.323,30.505) 0(144.323,30.505) 0(144.323,114.148) 0(144.323,114.148) 0(144.323,114.148)

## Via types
v1: diameter 0.45, hole 0.2, Top Layer to Bottom Layer, tented both sides, 995 vias
v2: diameter 0.406, hole 0.254, Top Layer to Bottom Layer, tented both sides, 118 vias
v3: diameter 1, hole 0.5, Top Layer to Bottom Layer, 116 vias
v4: diameter 0.5, hole 0.3, Top Layer to Bottom Layer, tented both sides, 16 vias
v5: diameter 0.406, hole 0.254, Top Layer to Bottom Layer, 2 vias

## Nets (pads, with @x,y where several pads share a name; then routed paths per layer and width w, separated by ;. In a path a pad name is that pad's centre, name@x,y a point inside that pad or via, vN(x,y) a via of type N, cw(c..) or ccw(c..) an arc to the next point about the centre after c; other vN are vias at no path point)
1P3_TX: C58.1 C59.2 C60.1 C63.2 L5.1 L7.1 L8.1 L9.1 U5.A7 U5.A8 U5.A9 U5.A10 | length 46.8
  Top Layer w0.2: C59.2@84.836,50.622 C58.1@84.836,49.479 84.836,48.404 84.934,48.306 v1(84.934,48.238) ; C59.2@84.963,50.495 85.75,51.283 85.75,54.33 U5.A9@86.754,55.334 ; U5.A7@86.754,53.734 U5.A8@86.754,54.534 U5.A9@86.754,55.334 ; U5.A10@86.754,56.134 U5.A9@86.754,55.334
  Bottom Layer w0.2: v1@84.938,48.209 84.226,47.498 84.226,45.923 85.014,45.136 102.438,45.136 104.484,47.181 C60.1@104.484,49.606 102.91,49.606 ccw(c102.91,49.346) L9.1@102.726,49.53 ; L7.1@102.624,53.823 102.624,47.737 ccw(c102.998,47.737) L8.1@102.734,47.473 ; L5.1@102.708,51.308 ccw(c103.015,51.615) 103.015,51.181 C63.2@104.502,51.181
AD9361_CLKOUT: U1.W18 U5.J6 | length 16.2
  Top Layer w0.127: v1@89.154,60.096 89.205,60.147 89.205,62.205 89.764,62.763 90.348,62.763 90.63,63.046 90.63,63.536 U1.W18@91.023,63.929 ; U5.J6@93.154,52.934 93.554,52.534 v1(93.558,52.534)
  Bottom Layer w0.127: v1(89.205,60.02) 89.267,59.958 89.502,59.958 90.983,58.478 90.983,53.574 92.412,52.144 93.167,52.144 v1(93.558,52.534)
AD9361_RST: RX4.1 U1.R19 U5.K5 | length 17.7
  Top Layer w0.127: v1(93.608,60.374) 93.696,60.374 93.88,60.189 95.056,60.189 95.285,60.417 95.285,61.274 95.005,61.553 94.682,61.553 94.567,61.438 94.162,61.438 93.817,61.784 93.817,62.723 U1.R19@94.21,63.116 ; U5.K5@93.954,52.134 93.962,52.134 94.347,51.749 v1(94.352,51.749)
  Layer 1 w0.127: v1(93.608,60.374) 93.534,60.299 93.472,60.299 93.472,57.739 93.167,57.433 93.167,56.591 93.167,54.774 93.164,54.771 93.164,53.699 93.964,52.899 93.964,52.124 94.34,51.749 v1(94.352,51.749)
  Bottom Layer w0.127: RX4.1@93.491,53.264 93.491,53.239 93.964,52.765 93.964,52.137 v1(94.352,51.749)
ADVDD10: C124.1 C125.1 C126.1 C127.2 C128.2 C130.2 C131.2 L6.2 U3.3 U3.9 U3.28 U3.36 U3.40 | length 38.6
  Top Layer w0.203: C125.1@127.763,82.068 127.788,82.068 128.569,82.85 128.821,82.85 130.176,84.204 U3.28@130.176,84.818 ; U3.9@130.176,90.618 v1@130.176,91.439 ; U3.3@132.576,90.618 132.578,90.621 132.578,91.485 v1(132.581,91.487) ; U3.36@133.376,84.818 133.376,84.006 134.722,82.659 C127.2@134.722,82.068 C127.2@134.748,82.042 ; U3.40@134.076,86.718 134.079,86.721 134.832,86.721 134.884,86.774 v1(134.951,86.774)
  Top Layer w0.508: C126.1@134.239,92.387 134.264,92.387 C126.1@134.31,92.341 ; v1(134.772,91.288) 134.31,91.75 C126.1@134.31,92.341 ; L6.2@136.296,92.278 136.234,92.341 C126.1@134.31,92.341
  Layer 2 w0.203: v1(128.263,82.604) 129.126,81.74 133.013,81.74 v1(134.359,83.086) ; v1(130.168,91.417) 130.6,91.849 132.193,91.849 132.555,91.487 v1(132.581,91.487)
  Bottom Layer w0.203: v1(130.168,91.417) 130.168,92.246 C130.2@130.175,92.253 ; v1(132.581,91.487) 132.581,92.246 C124.1@132.588,92.253 133.807,92.253 v1(134.772,91.288) 135.814,90.246 135.814,87.637 v1(134.951,86.774) ; v1(134.359,83.086) 134.953,83.086 135.407,83.541 135.407,85.968 ; C128.2@135.821,85.529 135.821,85.554 135.407,85.968 ; C131.2@135.821,86.698 135.745,86.774 v1(134.951,86.774) ; v1(134.951,86.774) 134.951,86.766 135.407,86.309 135.407,85.968
CB: *.6 R58.1 | length 1.6
  Top Layer w0.3: R58.1@97.123,113.767 97.125,113.769 98.737,113.769 *.6@98.74,113.772
CTRL_IN0: U1.G20 U5.C5 | length 35.2
  Top Layer w0.127: v1(87.954,51.734) U5.C5@88.354,52.134 ; U1.G20@100.61,62.32 v1@101.003,61.927
  Bottom Layer w0.127: v1(87.954,51.734) 86.742,51.734 85.979,50.971 85.979,47.232 86.938,46.274 95.746,46.274 98.679,49.207 98.679,54.109 100.279,55.709 100.279,61.265 100.942,61.927 v1(101.008,61.927)
CTRL_IN1: U1.D20 U5.C6 | length 39.4
  Top Layer w0.127: v1(87.954,52.534) U5.C6@88.354,52.934 ; v1(102.794,60.833) 103.353,61.392 103.353,61.978 103.011,62.319 103.01,62.319 U1.D20@103.01,62.32
  Bottom Layer w0.127: v1(87.954,52.534) 86.818,52.534 85.522,51.238 85.522,47.043 86.771,45.794 95.945,45.794 99.136,48.985 99.136,53.92 100.736,55.52 100.736,60.528 101.041,60.833 v1(102.794,60.833)
CTRL_IN2: U1.F20 U5.D6 | length 37.9
  Top Layer w0.127: v1(88.738,52.534) 88.754,52.534 U5.D6@89.154,52.934 ; U1.F20@101.41,62.32 v1@101.803,61.927
  Bottom Layer w0.127: v1(88.738,52.534) 88.348,52.144 86.829,52.144 85.75,51.066 85.75,47.138 86.866,46.022 95.85,46.022 98.908,49.08 98.908,54.014 100.508,55.614 100.508,61.151 100.876,61.519 101.399,61.519 v1(101.807,61.927)
CTRL_IN3: U1.H20 U5.D5 | length 34.7
  Top Layer w0.127: v1(88.738,51.734) 88.754,51.734 U5.D5@89.154,52.134 ; U1.H20@99.81,62.32 v1@100.203,61.927
  Bottom Layer w0.127: v1(88.738,51.734) 88.312,51.308 86.639,51.308 86.208,50.876 86.208,47.327 87.027,46.507 95.649,46.507 98.168,49.025 ; 98.171,49.022 98.45,49.301 98.45,54.204 100.051,55.804 100.051,61.359 100.203,61.512 100.203,61.922 v1(100.208,61.927)
CTRL_OUT0: U1.V17 U5.D4 | length 37.7
  Top Layer w0.127: v1(88.754,50.934) U5.D4@89.154,51.334 ; v1@91.43,64.336 U1.V17@91.823,64.729
  Bottom Layer w0.127: v1(88.754,50.934) 89.129,51.309 89.129,52.696 88.699,53.126 86.225,53.126 84.633,54.718 84.633,65.862 88.766,69.995 92.271,69.995 92.761,70.485 93.167,70.485 93.497,70.155 93.497,69.825 93.396,69.723 93.396,68.859 93.387,68.85 93.387,68.088 93.19,67.892 92.829,67.892 92.601,67.663 92.601,67.325 92.608,67.318 92.608,66.446 92.481,66.319 91.973,66.319 91.745,66.091 91.745,65.659 91.846,65.557 91.846,64.795 91.43,64.379 v1(91.43,64.332)
CTRL_OUT1: U1.T14 U5.E4 | length 34.7
  Top Layer w0.127: v1(89.554,50.934) U5.E4@89.954,51.334 ; v1@93.017,66.727 U1.T14@93.41,67.12
  Bottom Layer w0.127: v1(89.554,50.934) 89.968,50.521 90.539,50.521 90.989,50.07 90.989,49.869 92.376,48.482 95.973,48.482 96.449,48.482 97.993,50.026 97.993,50.502 97.993,55.419 98.895,56.321 98.895,60.456 97.942,61.408 97.942,64.661 97.688,64.915 97.688,64.948 97.587,65.049 97.587,65.938 96.736,66.789 96.304,66.789 95.885,67.208 95.885,67.666 95.64,67.911 93.583,67.911 93.381,67.709 93.381,67.129 93.017,66.764 v1(93.017,66.723)
CTRL_OUT2: U1.T15 U5.E5 | length 33.9
  Top Layer w0.127: v1(89.554,51.734) U5.E5@89.954,52.134 ; v1@93.017,65.927 U1.T15@93.41,66.32
  Bottom Layer w0.127: v1(89.554,51.734) 89.981,51.308 90.676,51.308 90.78,51.204 90.78,50.648 91.218,50.209 91.218,49.964 92.471,48.71 95.831,48.71 96.354,48.71 97.765,50.121 97.765,50.644 97.765,55.514 98.666,56.416 98.666,60.361 97.714,61.313 97.714,64.56 97.561,64.712 97.561,64.719 97.333,64.948 97.333,65.811 96.584,66.561 96.152,66.561 95.596,67.116 93.691,67.116 93.463,66.887 93.463,66.882 93.444,66.862 93.444,66.413 93.017,65.986 v1(93.017,65.923)
CTRL_OUT3: U1.P14 U5.E6 | length 31
  Top Layer w0.127: v1(89.554,52.534) U5.E6@89.954,52.934 ; v1@94.616,66.727 U1.P14@95.01,67.12
  Bottom Layer w0.127: v1(89.554,52.534) 89.579,52.534 89.967,52.146 90.576,52.146 91.043,51.68 91.043,50.708 91.447,50.304 91.447,50.058 92.566,48.939 96.259,48.939 97.536,50.216 97.536,55.609 98.438,56.51 98.438,60.266 97.485,61.219 97.485,64.465 96.999,64.951 96.999,65.605 96.387,66.217 95.168,66.217 94.662,66.723 v1(94.616,66.723)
